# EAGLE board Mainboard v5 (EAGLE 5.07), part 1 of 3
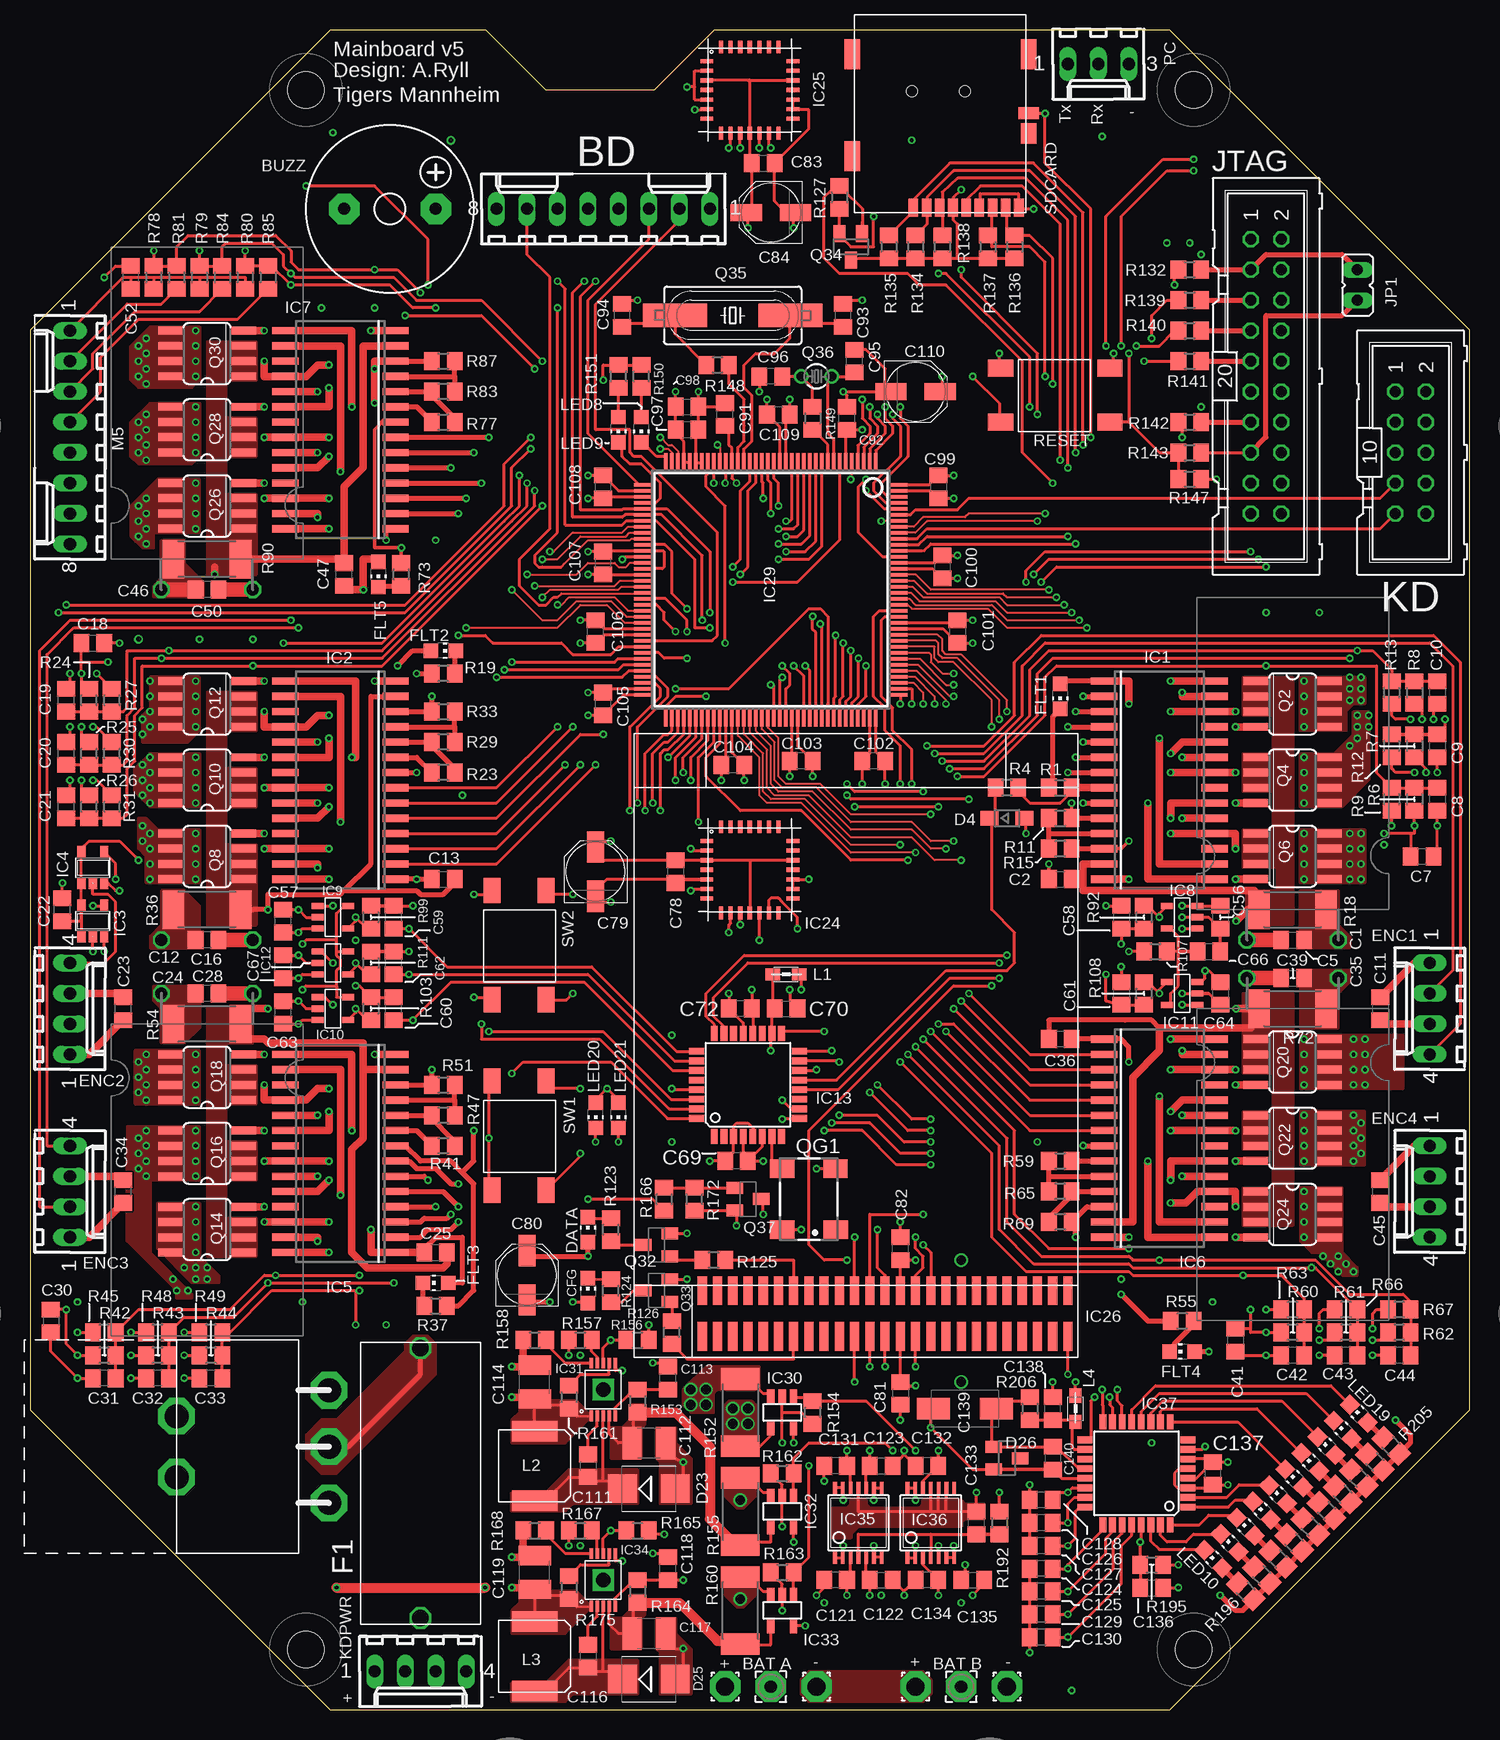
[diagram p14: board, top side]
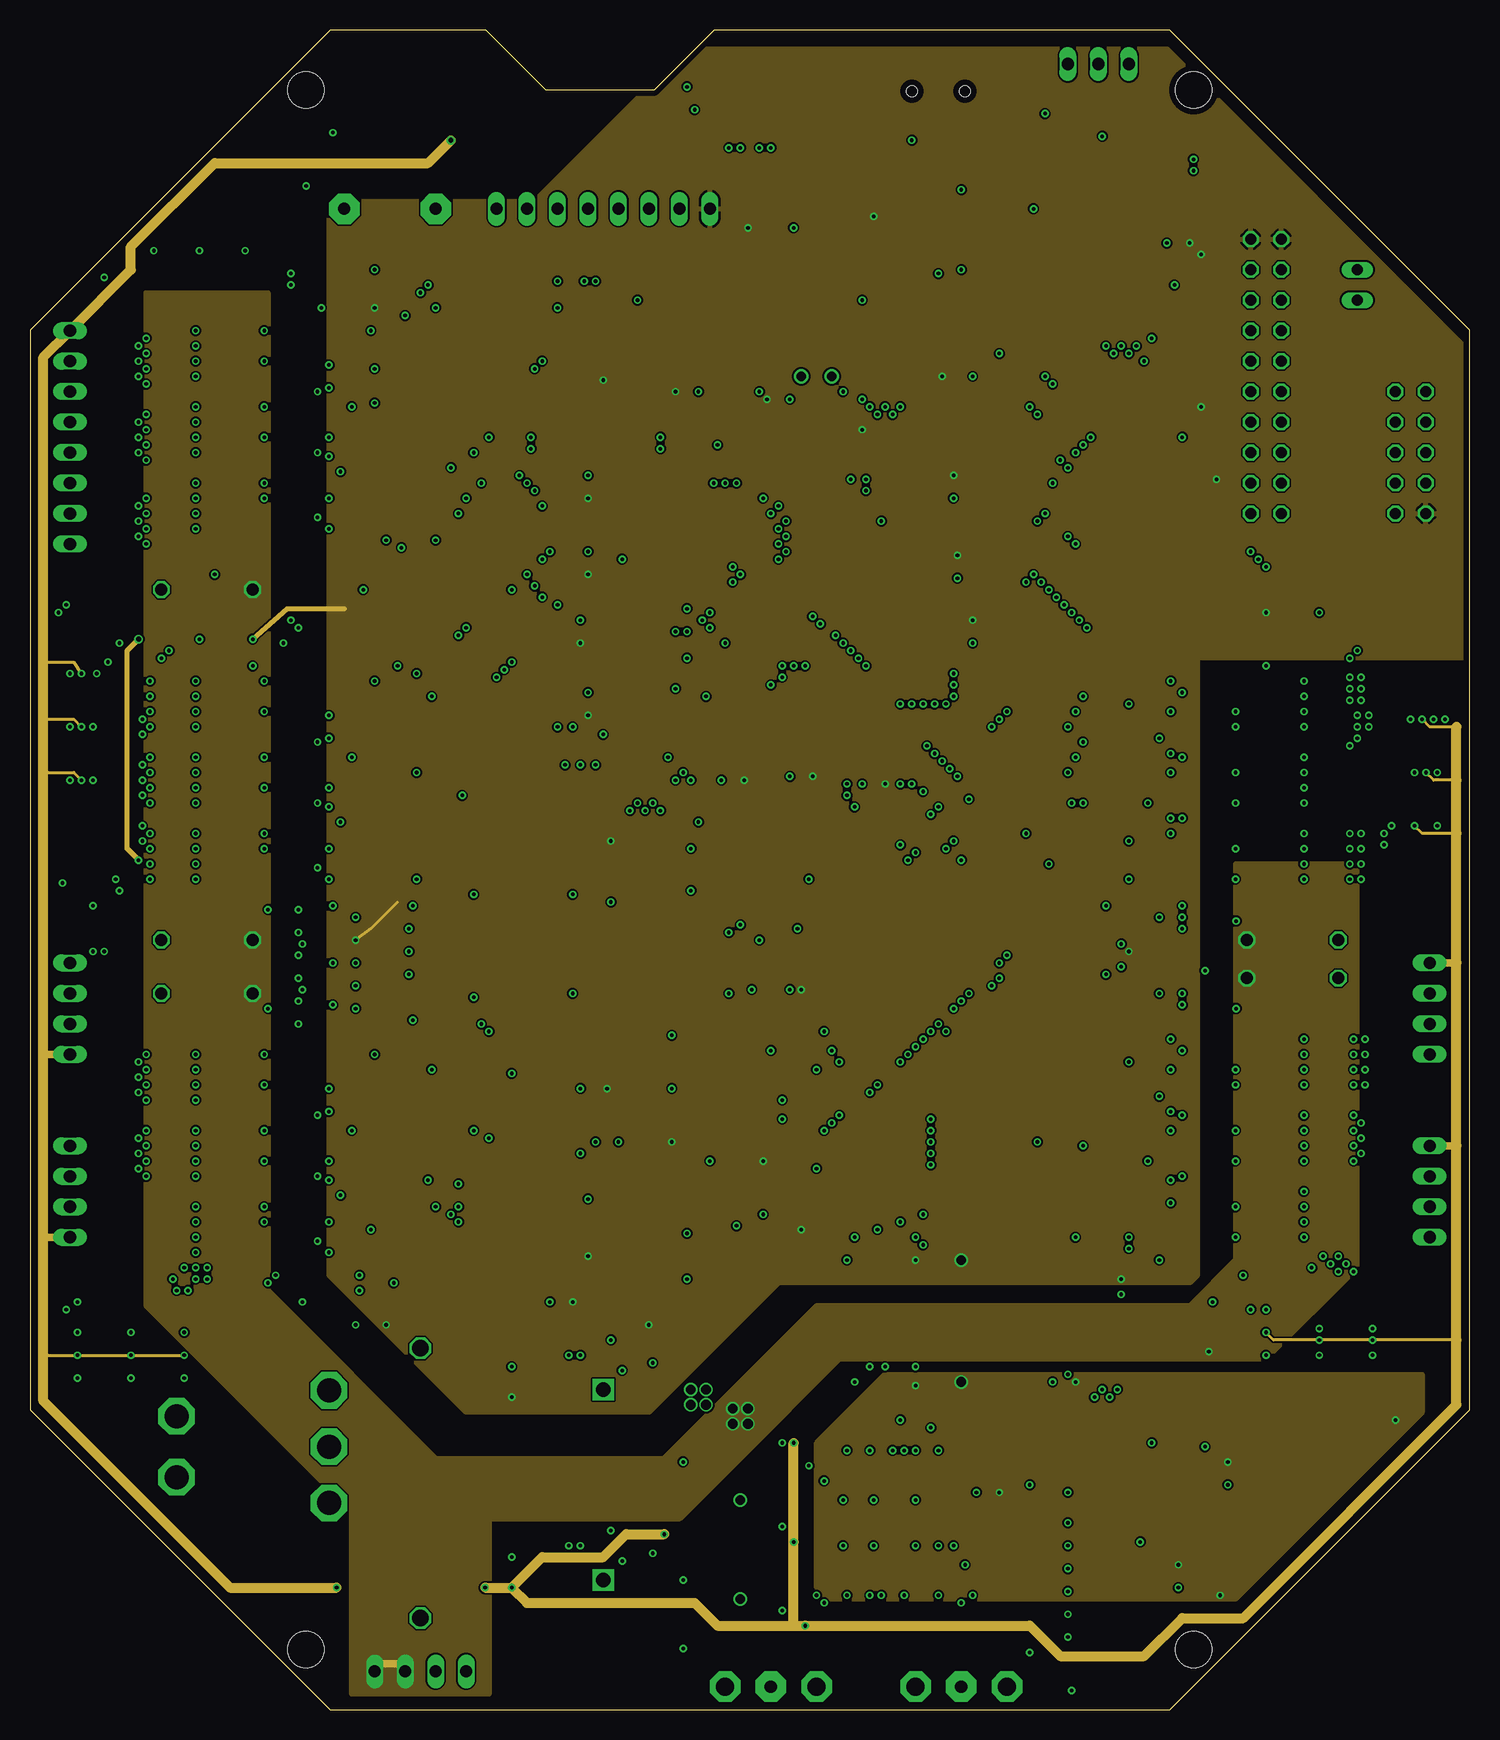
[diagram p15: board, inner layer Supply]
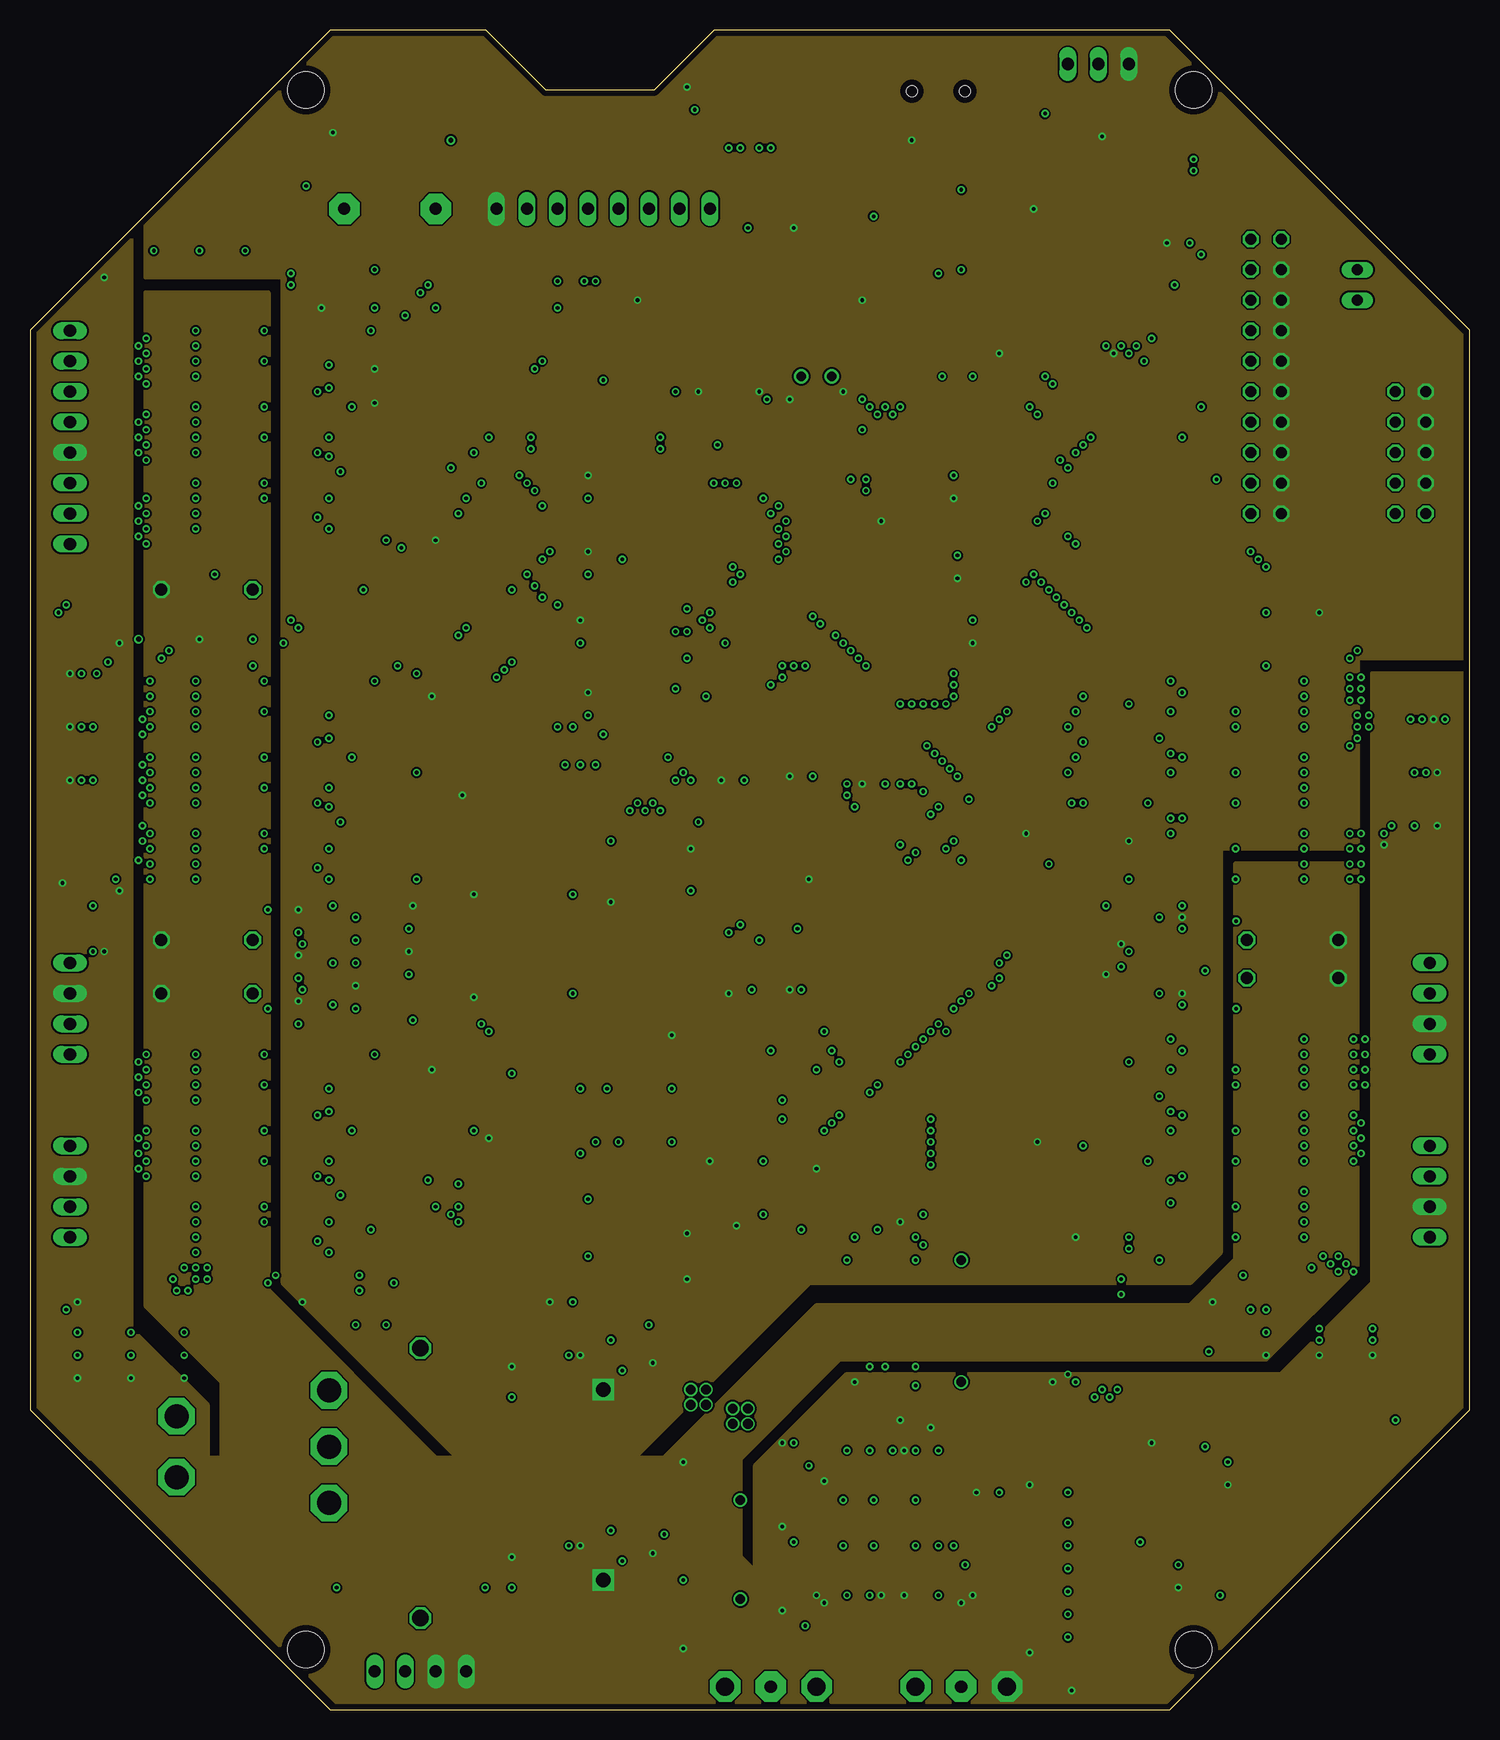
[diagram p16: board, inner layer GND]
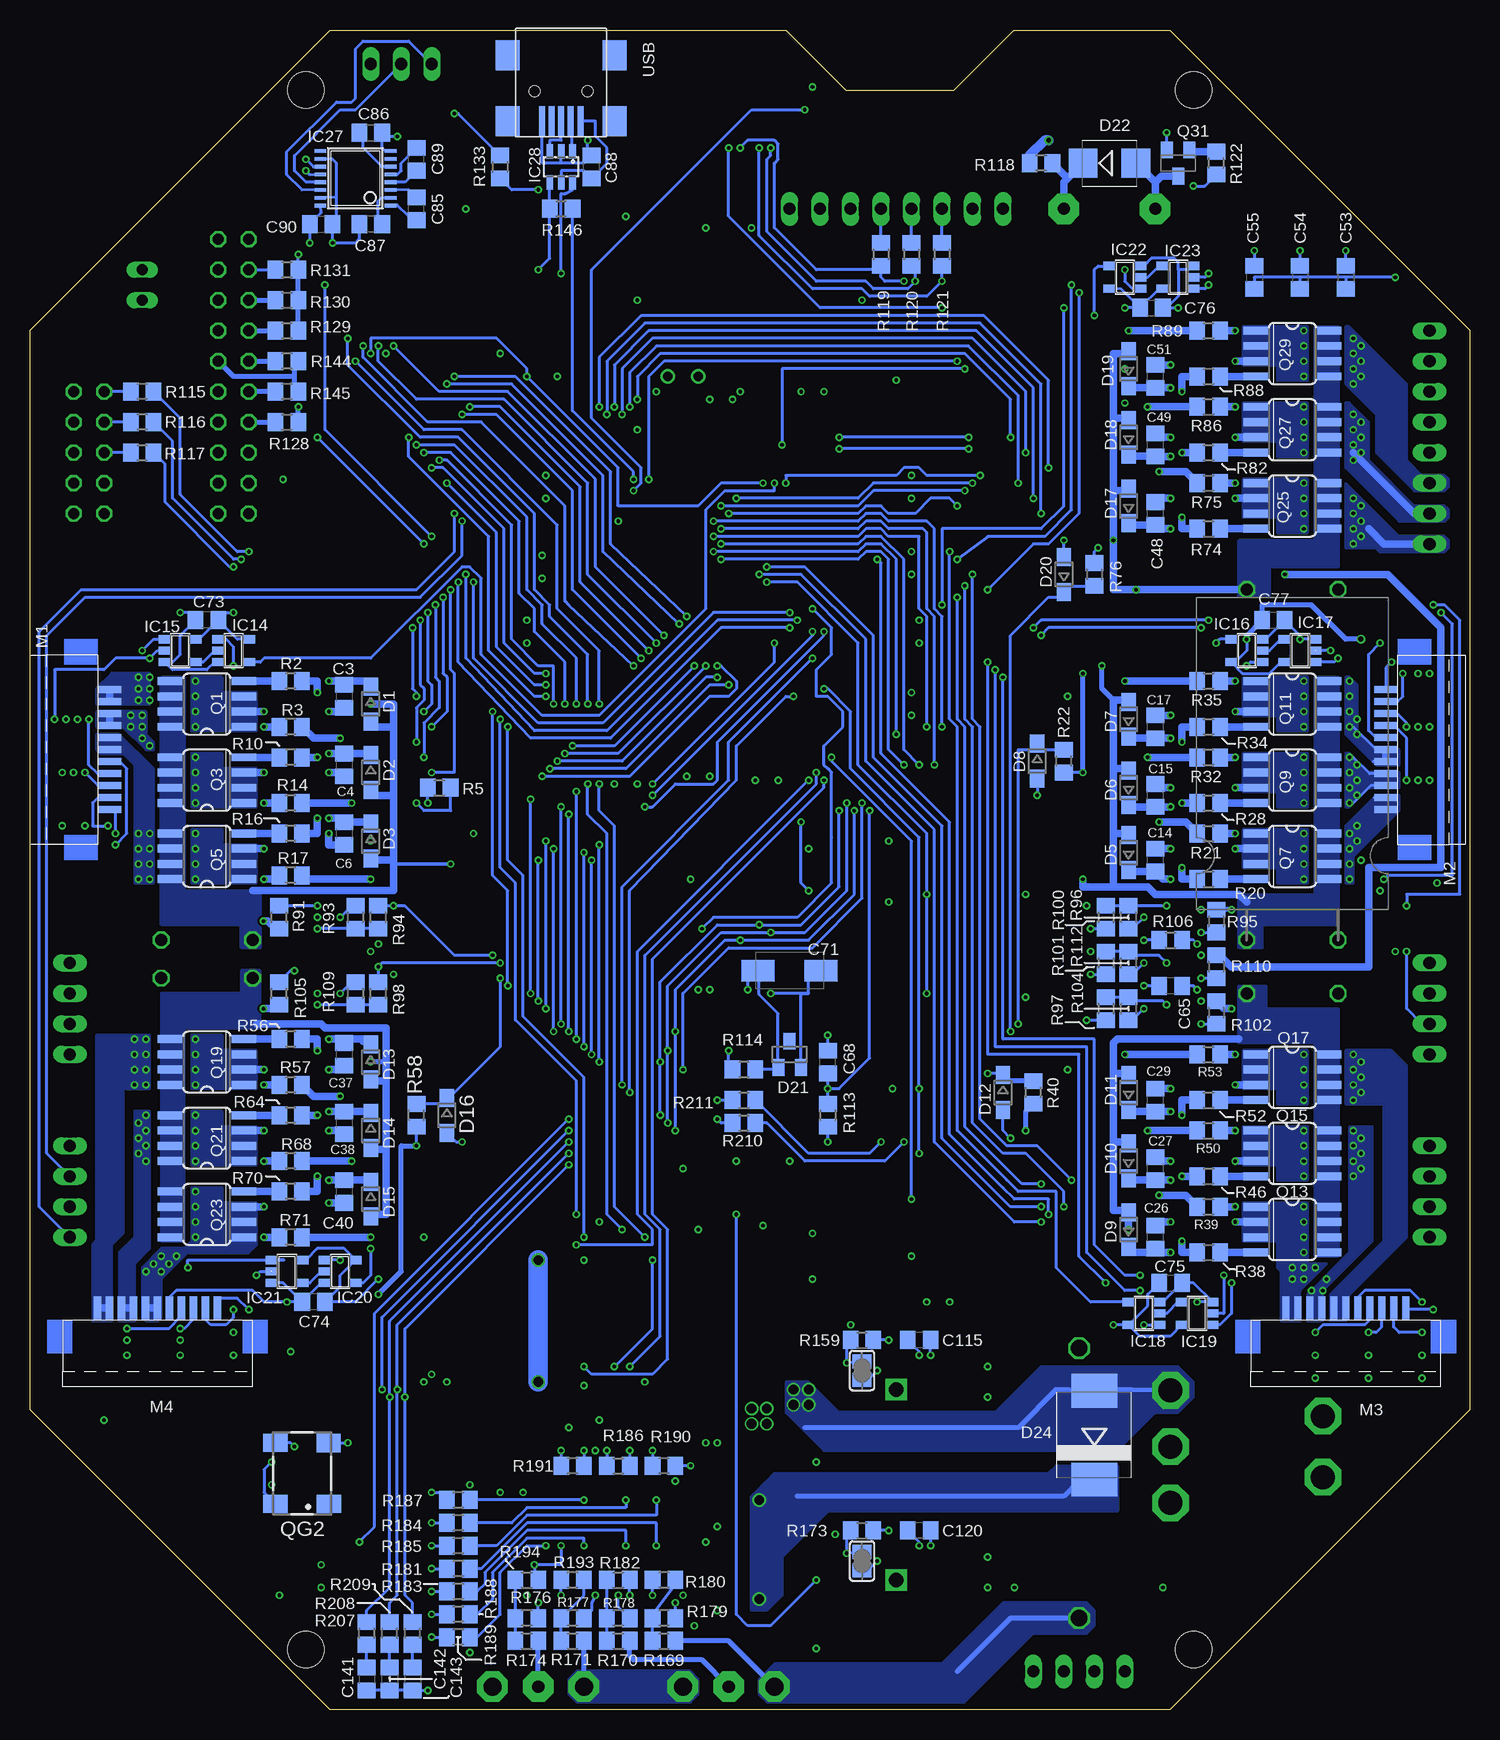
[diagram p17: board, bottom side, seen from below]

Size 120 x 140 mm. Coordinates in mm from the lower left corner, seen from the top.
Outline: 25,0 95,0 120,25 120,115 95,140 57,140 52,135 43,135 38,140 25,140 0,115 0,25 25,0
Copper layers (1+2*15+16): Top 0.035mm / dielectric 1.5mm / Supply 0.035mm / dielectric 0.15mm / GND 0.035mm / dielectric 0.2mm / Bottom 0.035mm
Design rules "PCB-POOL *": minimum track width 6mil, minimum drill 12mil, track to track 6mil, track to pad 6mil, pad to pad 6mil, via to via 6mil, smd to smd 6mil, copper to edge 20mil, drill to drill 8mil, minimum pad ring 8mil, minimum via ring 6mil, stop-mask expansion 3mil, vias tented up to drill 0mil, thermal gap 8mil
Net classes: 0 default: width 0.152 mm, clearance 0.152 mm
Holes 3 mm at 23,5 97,5 97,135 23,135
bKeepout: area 121.5,103.5 to 128.5,110.5

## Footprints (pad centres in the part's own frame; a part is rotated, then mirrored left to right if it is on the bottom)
2,54/1,0 = drill 1.016 pad 2.54 octagon: 1 0,0
2,54/1,5 = drill 1.5 pad 2.54 octagon: P$1 0,0
6410-08 = drill 1.016 long: 1 8.89,0; 2 6.35,0; 3 3.81,0; 4 1.27,0; 5 -1.27,0; 6 -3.81,0; 7 -6.35,0; 8 -8.89,0
F/CM12P = drill 1.016 pad 2.54 octagon: + 3.81,0; - -3.81,0
C25-16L = drill 1 octagon: A -3.81,-2.54; B 3.81,-2.54
C0805 = smd 1.3 x 1.5: 1 -0.95,0; 2 0.95,0
C/6032-28W = smd 2.75 x 1.8: + 2.625,0; - -2.625,0
PANASONIC_C = smd 2.6 x 1.4: + 2.05,0; - -2.05,0
C1210 = smd 1.6 x 2.7: 1 -1.4,0; 2 1.4,0
CHIP-LED0805 = smd 1.2 x 1.2: A 0,-1.05; C 0,1.05
SOD323-W = smd 1.5 x 1.2: A 1.45,0; C -1.45,0
SOT23 = smd 1 x 1.4: 1 -0.95,-1.1; 2 0.95,-1.1; 3 0,1.1
SMB = smd 2.4 x 2.4: A 2.2,0; C -2.2,0
SMC = smd 2.8 x 3.8: A 3.7,0; C -3.7,0
6410-04 = drill 1.016 long: 1 3.81,0; 2 1.27,0; 3 -1.27,0; 4 -3.81,0
FUSE20X5-2 = drill 1.4 octagon: P$1 0,0; P$2 22.5,0
SO28W = smd 0.6 x 2.2: 1 -8.255,-4.6; 2 -6.985,-4.6; 3 -5.715,-4.6; 4 -4.445,-4.6; 5 -3.175,-4.6; 6 -1.905,-4.6; 7 -0.635,-4.6; 8 0.635,-4.6; 9 1.905,-4.6; 10 3.175,-4.6; 11 4.445,-4.6; 12 5.715,-4.6; 13 6.985,-4.6; 14 8.255,-4.6; 15 8.255,4.6; 16 6.985,4.6; 17 5.715,4.6; 18 4.445,4.6; 19 3.175,4.6; 20 1.905,4.6; 21 0.635,4.6; 22 -0.635,4.6; 23 -1.905,4.6; 24 -3.175,4.6; 25 -4.445,4.6; 26 -5.715,4.6; 27 -6.985,4.6; 28 -8.255,4.6
SOT23-5 = smd 0.69 x 0.99: 1 -0.95,-1.29; 2 0,-1.29; 3 0.95,-1.29; 4 0.95,1.3; 5 -0.95,1.3
SOT23-5' = smd 1.016 x 0.508: 1 -1.27,0.953; 2 -1.27,0; 3 -1.27,-0.953; 4 1.27,-0.953; 5 1.27,0.953
TQFP32-08 = smd 1.27 x 0.559: 1 -4.293,2.8; 2 -4.293,2; 3 -4.293,1.2; 4 -4.293,0.4; 5 -4.293,-0.4; 6 -4.293,-1.2; 7 -4.293,-2; 8 -4.293,-2.8; 17 4.293,-2.8; 18 4.293,-2; 19 4.293,-1.2; 20 4.293,-0.4; 21 4.293,0.4; 22 4.293,1.2; 23 4.293,2; 24 4.293,2.8 | smd 0.559 x 1.27: 9 -2.8,-4.293; 10 -2,-4.293; 11 -1.2,-4.293; 12 -0.4,-4.293; 13 0.4,-4.293; 14 1.2,-4.293; 15 2,-4.293; 16 2.8,-4.293; 25 2.8,4.293; 26 2,4.293; 27 1.2,4.293; 28 0.4,4.293; 29 -0.4,4.293; 30 -1.2,4.293; 31 -2,4.293; 32 -2.8,4.293
QFPN-28 = smd 1.05 x 0.35: 1 -3.6,2.4; 2 -3.6,1.6; 3 -3.6,0.8; 4 -3.6,0; 5 -3.6,-0.8; 6 -3.6,-1.6; 7 -3.6,-2.4; 15 3.6,-2.4; 16 3.6,-1.6; 17 3.6,-0.8; 18 3.6,0; 19 3.6,0.8; 20 3.6,1.6; 21 3.6,2.4 | smd 0.35 x 1.05: 8 -2.4,-3.6; 9 -1.6,-3.6; 10 -0.8,-3.6; 11 0,-3.6; 12 0.8,-3.6; 13 1.6,-3.6; 14 2.4,-3.6; 22 2.4,3.6; 23 1.6,3.6; 24 0.8,3.6; 25 0,3.6; 26 -0.8,3.6; 27 -1.6,3.6; 28 -2.4,3.6
PINHEAD-1.27-50 = smd 2.4 x 0.76: 1 2.54,0; 2 -1.27,0; 3 2.54,-1.27; 4 -1.27,-1.27; 5 2.54,-2.54; 6 -1.27,-2.54; 7 2.54,-3.81; 8 -1.27,-3.81; 9 2.54,-5.08; 10 -1.27,-5.08; 11 2.54,-6.35; 12 -1.27,-6.35; 13 2.54,-7.62; 14 -1.27,-7.62; 15 2.54,-8.89; 16 -1.27,-8.89; 17 2.54,-10.16; 18 -1.27,-10.16; 19 2.54,-11.43; 20 -1.27,-11.43; 21 2.54,-12.7; 22 -1.27,-12.7; 23 2.54,-13.97; 24 -1.27,-13.97; 25 2.54,-15.24; 26 -1.27,-15.24; 27 2.54,-16.51; 28 -1.27,-16.51; 29 2.54,-17.78; 30 -1.27,-17.78; 31 2.54,-19.05; 32 -1.27,-19.05; 33 2.54,-20.32; 34 -1.27,-20.32; 35 2.54,-21.59; 36 -1.27,-21.59; 37 2.54,-22.86; 38 -1.27,-22.86; 39 2.54,-24.13; 40 -1.27,-24.13; 41 2.54,-25.4; 42 -1.27,-25.4; 43 2.54,-26.67; 44 -1.27,-26.67; 45 2.54,-27.94; 46 -1.27,-27.94; 47 2.54,-29.21; 48 -1.27,-29.21; 49 2.54,-30.48; 50 -1.27,-30.48
TSSOP16 = smd 0.305 x 0.991: 1 -2.275,-2.918; 2 -1.625,-2.918; 3 -0.975,-2.918; 4 -0.325,-2.918; 5 0.325,-2.918; 6 0.975,-2.918; 7 1.625,-2.918; 8 2.275,-2.918; 9 2.275,2.918; 10 1.625,2.918; 11 0.975,2.918; 12 0.325,2.918; 13 -0.325,2.918; 14 -0.975,2.918; 15 -1.625,2.918; 16 -2.275,2.918
SOT23-6L = smd 0.55 x 1.2: 1 -0.95,-1.3; 2 0,-1.3; 3 0.95,-1.3; 4 0.95,1.3; 5 0,1.3; 6 -0.95,1.3
SQFP-S-20X20-144 = smd 0.3 x 1.6: 1 -8.75,-10.6; 2 -8.25,-10.6; 3 -7.75,-10.6; 4 -7.25,-10.6; 5 -6.75,-10.6; 6 -6.25,-10.6; 7 -5.75,-10.6; 8 -5.25,-10.6; 9 -4.75,-10.6; 10 -4.25,-10.6; 11 -3.75,-10.6; 12 -3.25,-10.6; 13 -2.75,-10.6; 14 -2.25,-10.6; 15 -1.75,-10.6; 16 -1.25,-10.6; 17 -0.75,-10.6; 18 -0.25,-10.6; 19 0.25,-10.6; 20 0.75,-10.6; 21 1.25,-10.6; 22 1.75,-10.6; 23 2.25,-10.6; 24 2.75,-10.6; 25 3.25,-10.6; 26 3.75,-10.6; 27 4.25,-10.6; 28 4.75,-10.6; 29 5.25,-10.6; 30 5.75,-10.6; 31 6.25,-10.6; 32 6.75,-10.6; 33 7.25,-10.6; 34 7.75,-10.6; 35 8.25,-10.6; 36 8.75,-10.6; 73 8.75,10.6; 74 8.25,10.6; 75 7.75,10.6; 76 7.25,10.6; 77 6.75,10.6; 78 6.25,10.6; 79 5.75,10.6; 80 5.25,10.6; 81 4.75,10.6; 82 4.25,10.6; 83 3.75,10.6; 84 3.25,10.6; 85 2.75,10.6; 86 2.25,10.6; 87 1.75,10.6; 88 1.25,10.6; 89 0.75,10.6; 90 0.25,10.6; 91 -0.25,10.6; 92 -0.75,10.6; 93 -1.25,10.6; 94 -1.75,10.6; 95 -2.25,10.6; 96 -2.75,10.6; 97 -3.25,10.6; 98 -3.75,10.6; 99 -4.25,10.6; 100 -4.75,10.6; 101 -5.25,10.6; 102 -5.75,10.6; 103 -6.25,10.6; 104 -6.75,10.6; 105 -7.25,10.6; 106 -7.75,10.6; 107 -8.25,10.6; 108 -8.75,10.6 | smd 1.6 x 0.3: 37 10.6,-8.75; 38 10.6,-8.25; 39 10.6,-7.75; 40 10.6,-7.25; 41 10.6,-6.75; 42 10.6,-6.25; 43 10.6,-5.75; 44 10.6,-5.25; 45 10.6,-4.75; 46 10.6,-4.25; 47 10.6,-3.75; 48 10.6,-3.25; 49 10.6,-2.75; 50 10.6,-2.25; 51 10.6,-1.75; 52 10.6,-1.25; 53 10.6,-0.75; 54 10.6,-0.25; 55 10.6,0.25; 56 10.6,0.75; 57 10.6,1.25; 58 10.6,1.75; 59 10.6,2.25; 60 10.6,2.75; 61 10.6,3.25; 62 10.6,3.75; 63 10.6,4.25; 64 10.6,4.75; 65 10.6,5.25; 66 10.6,5.75; 67 10.6,6.25; 68 10.6,6.75; 69 10.6,7.25; 70 10.6,7.75; 71 10.6,8.25; 72 10.6,8.75; 109 -10.6,8.75; 110 -10.6,8.25; 111 -10.6,7.75; 112 -10.6,7.25; 113 -10.6,6.75; 114 -10.6,6.25; 115 -10.6,5.75; 116 -10.6,5.25; 117 -10.6,4.75; 118 -10.6,4.25; 119 -10.6,3.75; 120 -10.6,3.25; 121 -10.6,2.75; 122 -10.6,2.25; 123 -10.6,1.75; 124 -10.6,1.25; 125 -10.6,0.75; 126 -10.6,0.25; 127 -10.6,-0.25; 128 -10.6,-0.75; 129 -10.6,-1.25; 130 -10.6,-1.75; 131 -10.6,-2.25; 132 -10.6,-2.75; 133 -10.6,-3.25; 134 -10.6,-3.75; 135 -10.6,-4.25; 136 -10.6,-4.75; 137 -10.6,-5.25; 138 -10.6,-5.75; 139 -10.6,-6.25; 140 -10.6,-6.75; 141 -10.6,-7.25; 142 -10.6,-7.75; 143 -10.6,-8.25; 144 -10.6,-8.75
SOT23-5'' = smd 0.6 x 1.2: 1 -0.95,-1.306; 2 0,-1.306; 3 0.95,-1.306; 4 0.95,1.306; 5 -0.95,1.306
MSOP10 = smd 0.9 x 0.3: 1 -2.2,1; 2 -2.2,0.5; 3 -2.2,0; 4 -2.2,-0.5; 5 -2.2,-1; 6 2.2,-1; 7 2.2,-0.5; 8 2.2,0; 9 2.2,0.5; 10 2.2,1 | drill 1.2 pad 1.8 square: 11 0,0
TSSOP14 = smd 0.305 x 0.991: 1 -1.95,-2.918; 2 -1.3,-2.918; 3 -0.65,-2.918; 4 0,-2.918; 5 0.65,-2.918; 6 1.3,-2.918; 7 1.95,-2.918; 8 1.95,2.918; 9 1.3,2.918; 10 0.65,2.918; 11 0,2.918; 12 -0.65,2.918; 13 -1.3,2.918; 14 -1.95,2.918
JP1 = drill 0.914 long: 1 0,-1.27; 2 0,1.27
ML20 = drill 0.914 octagon: 1 -11.43,-1.27; 2 -11.43,1.27; 3 -8.89,-1.27; 4 -8.89,1.27; 5 -6.35,-1.27; 6 -6.35,1.27; 7 -3.81,-1.27; 8 -3.81,1.27; 9 -1.27,-1.27; 10 -1.27,1.27; 11 1.27,-1.27; 12 1.27,1.27; 13 3.81,-1.27; 14 3.81,1.27; 15 6.35,-1.27; 16 6.35,1.27; 17 8.89,-1.27; 18 8.89,1.27; 19 11.43,-1.27; 20 11.43,1.27
ML10 = drill 0.914 octagon: 1 -5.08,-1.27; 2 -5.08,1.27; 3 -2.54,-1.27; 4 -2.54,1.27; 5 0,-1.27; 6 0,1.27; 7 2.54,-1.27; 8 2.54,1.27; 9 5.08,-1.27; 10 5.08,1.27
0805 = smd 1.2 x 1: 1 -1.1,0; 2 1.1,0
L-ELL6 = smd 1.7 x 3.8: P$1 -2.9,0; P$2 2.9,0
MOLEX11 = smd 0.6 x 1.9: 1 5,3; 2 4,3; 3 3,3; 4 2,3; 5 1,3; 6 0,3; 7 -1,3; 8 -2,3; 9 -3,3; 10 -4,3; 11 -5,3
6410-03 = drill 1.016 long: 1 2.54,0; 2 0,0; 3 -2.54,0
SOIC8 = smd 0.66 x 2.032: 1 -1.905,-3.073; 2 -0.635,-3.073; 3 0.635,-3.073; 4 1.905,-3.073; 5 1.905,3.073; 6 0.635,3.073; 7 -0.635,3.073; 8 -1.905,3.073
SOT23-BEC = smd 1 x 1.4: B -0.95,-1.1; C 0,1.1; E 0.95,-1.1
HC49UP = smd 5.334 x 1.93: 1 -4.826,0; 2 4.826,0
TC26V = drill 0.813 round: 1 -1.27,0; 2 1.27,0
SM77H = smd 1.524 x 2.032: 1 -2.545,-2.232; 2 2.535,-2.212; 3 2.545,2.232; 4 -2.535,2.212
R0805 = smd 1.3 x 1.5: 1 -0.95,0; 2 0.95,0
R2512 = smd 1.8 x 3.2: 1 -2.8,0; 2 2.8,0
BUTTON4 = smd 1.4 x 2.1: 1 4.5,9.1; 2 4.5,0; 3 0,9.1; 4 0,0
MICRO-SD = smd 0.8 x 1.5: 1 4.9,0.4; 2 6,0.4; 3 7.1,0.4; 4 8.2,0.4; 5 9.3,0.4; 6 10.4,0.4; 7 11.5,0.4; 8 12.6,0.4; COM 13.7,0.4 | smd 1.7 x 1: CD 14.5,8.3 | smd 1.3 x 2.5: P$10 14.5,13.2; P$11 -0.2,13.2; P$12 -0.2,4.7 | smd 1.3 x 1.7: P$14 14.5,6.6
SJ = smd 1.168 x 1.6: 1 -0.762,0; 2 0.762,0
TYCO-SW = drill 2 pad 3.048 octagon: 1 -4.699,12.7; 2 0,12.7; 3 4.699,12.7; MNT1 -2.54,0; MNT2 2.54,0
USB-BMINI = smd 2.5 x 0.5: 1 0,1.6; 2 0,0.8; 3 0,0; 4 0,-0.8; 5 0,-1.6 | smd 2.5 x 2: P$6 0,4.45; P$7 0,-4.45; P$8 -5.5,4.45; P$9 -5.5,-4.45 | hole 0.9: -2.5,2.2; -2.5,-2.2

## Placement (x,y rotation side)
BAT1#  [2,54/1,0]  61.75,1.91 0 top
BAT1+  [2,54/1,5]  57.94,1.91 0 top
BAT1-  [2,54/1,5]  65.56,1.91 0 top
BAT2#  [2,54/1,0]  77.63,1.91 0 top
BAT2+  [2,54/1,5]  73.82,1.91 0 top
BAT2-  [2,54/1,5]  81.44,1.91 0 top
BD  MOLEX8  [6410-08]  47.78,125.09 0 top
BUZZ  F/CM12P  [F/CM12P]  30.01,125.09 0 top
C1  3300u/25V  [C25-16L]  105.25,66.67 0 top
C2  4u7  [C0805]  85.89,69.22 0 top
C3  4u7  [C0805]  93.82,84.45 270 bottom
C4  4u7  [C0805]  93.82,78.74 270 bottom
C5  10u  [C0805]  105.25,64.14 0 top
C6  4u7  [C0805]  93.82,73.03 270 bottom
C7  100n  [C0805]  116.05,71.12 0 top
C8  1n  [C0805]  117.32,75.88 270 top
C9  1n  [C0805]  117.32,80.33 270 top
C10  1n  [C0805]  117.32,84.77 270 top
C11  100n  [C0805]  112.56,58.42 270 top
C12  3300u/25V  [C25-16L]  14.77,66.67 0 bottom
C13  4u7  [C0805]  34.45,69.22 0 top
C14  4u7  [C0805]  26.2,70.8 90 bottom
C15  4u7  [C0805]  26.2,76.2 90 bottom
C16  10u  [C0805]  14.77,64.14 180 top
C17  4u7  [C0805]  26.2,81.92 90 bottom
C18  100n  [C0805]  5.24,88.9 0 top
C19  1n  [C0805]  3.02,84.14 90 top
C20  1n  [C0805]  3.02,79.69 90 top
C21  1n  [C0805]  3.02,75.25 90 top
C22  100n  [C0805]  2.7,66.67 90 top
C23  100n  [C0805]  7.78,58.42 90 top
C24  3300u/25V  [C25-16L]  14.77,57.15 180 top
C25  4u7  [C0805]  33.81,38.1 0 top
C26  4u7  [C0805]  26.2,39.37 90 bottom
C27  4u7  [C0805]  26.2,45.09 90 bottom
C28  10u  [C0805]  14.77,59.69 180 top
C29  4u7  [C0805]  26.2,50.8 90 bottom
C30  100n  [C0805]  1.75,32.38 270 top
C31  1n  [C0805]  6.19,27.62 180 top
C32  1n  [C0805]  10.64,27.62 180 top
C33  1n  [C0805]  15.08,27.62 180 top
C34  100n  [C0805]  7.78,43.18 90 top
C35  3300u/25V  [C25-16L]  105.25,58.42 180 top
C36  4u7  [C0805]  85.89,55.88 180 top
C37  4u7  [C0805]  93.82,54.61 270 bottom
C38  4u7  [C0805]  93.82,48.9 270 bottom
C39  10u  [C0805]  105.25,60.96 0 top
C40  4u7  [C0805]  93.82,43.18 270 bottom
C41  100n  [C0805]  100.49,30.8 270 top
C42  1n  [C0805]  105.25,29.53 180 top
C43  1n  [C0805]  109.7,29.53 180 top
C44  1n  [C0805]  114.14,29.53 180 top
C45  100n  [C0805]  112.56,43.18 270 top
C46  3300u/25V  [C25-16L]  14.77,95.89 0 top
C47  4u7  [C0805]  26.2,94.61 90 top
C48  4u7  [C0805]  26.2,99.69 90 bottom
C49  4u7  [C0805]  26.2,105.41 90 bottom
C50  10u  [C0805]  14.77,93.34 180 top
C51  4u7  [C0805]  26.2,111.12 90 bottom
C52  100n  [C0805]  8.41,119.38 90 top
C53  1n  [C0805]  10.32,119.38 270 bottom
C54  1n  [C0805]  14.13,119.38 270 bottom
C55  1n  [C0805]  17.94,119.38 270 bottom
C56  1u  [C0805]  99.22,66.04 270 top
C57  1u  [C0805]  21.11,65.72 90 top
C58  100n  [C0805]  90.97,66.04 270 top
C59  100n  [C0805]  30.32,66.04 90 top
C60  100n  [C0805]  30.32,58.42 90 top
C61  100n  [C0805]  90.97,59.69 270 top
C62  100n  [C0805]  30.32,62.23 90 top
C63  1u  [C0805]  21.11,58.1 90 top
C64  1u  [C0805]  99.22,59.69 270 top
C65  4u7  [C0805]  24.92,60.33 180 bottom
C66  4u7  [C0805]  98.27,63.18 0 top
C67  1u  [C0805]  21.11,61.91 90 top
C68  100n  [C0805]  53.5,53.98 90 bottom
C69  100n  [C0805]  58.9,45.72 180 top
C70  100n  [C0805]  63.03,58.42 0 top
C71  10u  [C/6032-28W]  56.67,61.59 180 bottom
C72  100n  [C0805]  59.22,58.42 180 top
C73  100n  [C0805]  105.25,90.81 180 bottom
C74  100n  [C0805]  96.36,33.97 180 bottom
C75  100n  [C0805]  24.92,35.56 0 bottom
C76  100n  [C0805]  26.51,116.84 0 bottom
C77  100n  [C0805]  16.35,90.81 0 bottom
C78  100n  [C0805]  53.82,69.85 270 top
C79  10u  [PANASONIC_C]  47.15,69.85 90 top
C80  10u  [PANASONIC_C]  41.44,36.2 90 top
C81  100n  [C0805]  72.55,26.35 270 top
C82  100n  [C0805]  72.55,38.42 90 top
C83  100n  [C0805]  61.12,128.91 0 top
C84  10u  [PANASONIC_C]  61.75,124.78 180 top
C85  100n  [C0805]  87.79,125.09 90 bottom
C86  100n  [C0805]  91.6,131.44 0 bottom
C87  100n  [C0805]  91.6,123.83 180 bottom
C88  100n  [C0805]  73.19,128.59 90 bottom
C89  100n  [C0805]  87.79,129.22 90 bottom
C90  100n  [C0805]  95.73,123.83 0 bottom
C91  100n  [C0805]  57.94,107.95 90 top
C92  100n  [C0805]  68.11,107.63 90 top
C93  18p  [C0805]  67.79,116.2 90 top
C94  18p  [C0805]  49.37,116.2 90 top
C95  6p  [C0805]  68.74,112.39 90 top
C96  6p  [C0805]  61.75,111.12 180 top
C97  1u  [C0805]  54.77,106.68 0 top
C98  100n  [C0805]  54.77,108.58 0 top
C99  100n  [C0805]  75.72,101.92 270 top
C100  100n  [C0805]  76.04,95.25 270 top
C101  100n  [C0805]  77.31,89.85 270 top
C102  100n  [C0805]  70.33,79.06 180 top
C103  100n  [C0805]  64.3,79.06 180 top
C104  100n  [C0805]  58.58,78.74 180 top
C105  100n  [C0805]  47.78,83.82 90 top
C106  100n  [C0805]  47.15,89.85 90 top
C107  100n  [C0805]  47.78,95.57 90 top
C108  100n  [C0805]  47.78,101.92 90 top
C109  100n  [C0805]  62.39,107.95 0 top
C110  10µ  [PANASONIC_C]  73.82,109.86 0 top
C111  470n  [C0805]  46.52,20.32 270 top
C112  10u  [C1210]  51.59,22.23 0 top
C113  100n  [C0805]  53.18,27.62 90 top
C114  47u  [C1210]  42.07,27.3 90 top
C115  470p  [C0805]  45.88,30.8 180 bottom
C116  470n  [C0805]  46.52,4.45 270 top
C117  10u  [C1210]  51.59,6.35 0 top
C118  100n  [C0805]  53.18,11.75 90 top
C119  47u  [C1210]  42.07,11.43 90 top
C120  470p  [C0805]  45.88,14.92 180 bottom
C121  100n  [C0805]  67.15,10.79 180 top
C122  100n  [C0805]  70.96,10.79 0 top
C123  100n  [C0805]  70.96,20.32 0 top
C124  100n  [C0805]  84.3,11.75 180 top
C125  100n  [C0805]  84.3,9.84 180 top
C126  100n  [C0805]  84.3,15.56 180 top
C127  100n  [C0805]  84.3,13.65 180 top
C128  100n  [C0805]  84.3,17.46 180 top
C129  100n  [C0805]  84.3,7.94 180 top
C130  100n  [C0805]  84.3,6.03 180 top
C131  100n  [C0805]  67.15,20.32 180 top
C132  100n  [C0805]  74.77,20.32 180 top
C133  4u7  [C0805]  78.9,15.56 90 top
C134  100n  [C0805]  74.77,10.79 180 top
C135  100n  [C0805]  78.58,10.79 0 top
C136  100n  [C0805]  93.5,10.16 0 top
C137  100n  [C0805]  98.58,19.68 270 top
C138  100n  [C0805]  85.25,25.08 90 top
C139  10u  [C/6032-28W]  77.95,25.08 0 top
C140  100n  [C0805]  85.25,20.95 270 top
C141  100p  [C0805]  91.92,2.54 270 bottom
C142  100p  [C0805]  90.01,2.54 270 bottom
C143  100p  [C0805]  88.11,2.54 270 bottom
CFG  rd, 2mA  [CHIP-LED0805]  46.52,34.92 0 top
D1  BAT41  [SOD323-W]  91.6,83.82 270 bottom
D2  BAT41  [SOD323-W]  91.6,78.11 270 bottom
D3  BAT41  [SOD323-W]  91.6,72.39 270 bottom
D4  Z-3.3V  [SOD323-W]  81.44,74.3 0 top
D5  BAT41  [SOD323-W]  28.42,71.44 90 bottom
D6  BAT41  [SOD323-W]  28.42,76.83 90 bottom
D7  BAT41  [SOD323-W]  28.42,82.55 90 bottom
D8  Z-3.3V  [SOD323-W]  36.04,79.06 270 bottom
D9  BAT41  [SOD323-W]  28.42,40.01 90 bottom
D10  BAT41  [SOD323-W]  28.42,45.72 90 bottom
D11  BAT41  [SOD323-W]  28.42,51.44 90 bottom
D12  Z-3.3V  [SOD323-W]  38.9,51.44 270 bottom
D13  BAT41  [SOD323-W]  91.6,53.98 270 bottom
D14  BAT41  [SOD323-W]  91.6,48.26 270 bottom
D15  BAT41  [SOD323-W]  91.6,42.55 270 bottom
D16  Z-3.3V  [SOD323-W]  85.25,49.53 270 bottom
D17  BAT41  [SOD323-W]  28.42,100.33 90 bottom
D18  BAT41  [SOD323-W]  28.42,106.05 90 bottom
D19  BAT41  [SOD323-W]  28.42,111.76 90 bottom
D20  Z-3.3V  [SOD323-W]  33.81,94.61 90 bottom
D21  LM4040-2.048  [SOT23]  56.67,54.61 0 bottom
D22  MBRS240  [SMB]  30.01,128.91 0 bottom
D23  MBRS240  [SMB]  51.59,18.41 0 top
D24  MBRS340  [SMC]  31.27,22.86 90 bottom
D25  MBRS240  [SMB]  51.59,2.54 0 top
D26  LM4040-2.048  [SOT23]  81.44,20.95 270 top
DATA  gr, 2mA  [CHIP-LED0805]  46.52,40.01 0 top
ENC1  22-27-2041-04  [6410-04]  116.68,58.42 90 top
ENC2  22-27-2041-04  [6410-04]  3.34,58.42 270 top
ENC3  22-27-2041-04  [6410-04]  3.34,43.18 270 top
ENC4  22-27-2041-04  [6410-04]  116.68,43.18 90 top
F1  [FUSE20X5-2]  32.55,7.62 90 top
FLT1  rd  [CHIP-LED0805]  85.89,84.45 180 top
FLT2  rd  [CHIP-LED0805]  34.45,88.27 270 top
FLT3  rd  [CHIP-LED0805]  33.81,35.56 90 top
FLT4  rd  [CHIP-LED0805]  96.05,29.84 90 top
FLT5  rd  [CHIP-LED0805]  29.05,94.61 180 top
IC1  IR2130S  [SO28W]  94.14,77.47 270 top
IC2  IR2130S  [SO28W]  25.88,77.47 90 top
IC3  74LVC1G08DBV  [SOT23-5]  5.24,65.72 0 top
IC4  74LVC1G08DBV  [SOT23-5]  5.24,70.17 0 top
IC5  IR2130S  [SO28W]  25.88,46.35 90 top
IC6  IR2130S  [SO28W]  94.14,47.62 270 top
IC7  IR2130S  [SO28W]  25.88,106.68 90 top
IC8  AD8691  [SOT23-5']  96.05,66.04 180 top
IC9  AD8691  [SOT23-5']  25.24,66.04 0 top
IC10  AD8691  [SOT23-5']  25.24,58.42 0 top
IC11  AD8691  [SOT23-5']  96.05,59.69 180 top
IC12  AD8691  [SOT23-5']  25.24,62.23 0 top
IC13  MEGA48/88/168-AU  [TQFP32-08]  59.85,52.07 90 top
IC14  74AHC1G86DBV  [SOT23-5]  103.03,88.27 270 bottom
IC15  74AHC1G86DBV  [SOT23-5]  107.47,88.27 270 bottom
IC16  74AHC1G86DBV  [SOT23-5]  18.57,88.27 90 bottom
IC17  74AHC1G86DBV  [SOT23-5]  14.13,88.27 90 bottom
IC18  74AHC1G86DBV  [SOT23-5]  27.15,33.02 90 bottom
IC19  74AHC1G86DBV  [SOT23-5]  22.7,33.02 90 bottom
IC20  74AHC1G86DBV  [SOT23-5]  94.14,36.51 270 bottom
IC21  74AHC1G86DBV  [SOT23-5]  98.58,36.51 270 bottom
IC22  74AHC1G86DBV  [SOT23-5]  28.73,119.38 90 bottom
IC23  74AHC1G86DBV  [SOT23-5]  24.29,119.38 90 bottom
IC24  LIS3LV02DQ  [QFPN-28]  60,70 0 top
IC25  LIS3LV02DQ  [QFPN-28]  60,135 0 top
IC26  HW86012  [PINHEAD-1.27-50]  56.04,32.38 90 top
IC27  MAX3232CUE  [TSSOP16]  92.87,127.64 90 bottom
IC28  USBLC6-2  [SOT23-6L]  75.72,128.59 180 bottom
IC29  [SQFP-S-20X20-144]  61.75,93.34 180 top
IC30  INA139  [SOT23-5'']  62.71,24.77 180 top
IC31  LT3480  [MSOP10]  47.78,26.67 90 top
IC32  INA139  [SOT23-5'']  62.71,16.51 180 top
IC33  INA139  [SOT23-5'']  62.71,8.26 180 top
IC34  LT3480  [MSOP10]  47.78,10.79 90 top
IC35  AD8648  [TSSOP14]  69.06,15.56 0 top
IC36  AD8648  [TSSOP14]  75.09,15.56 0 top
IC37  MEGA48/88/168-AU  [TQFP32-08]  92.23,19.68 180 top
JP1  [JP1]  110.65,118.75 0 top
JTAG  [ML20]  103.03,111.12 270 top
KD  [ML10]  115.09,104.78 270 top
KDPWR  MOLEX4  [6410-04]  32.55,3.17 180 top
L1  10u  [0805]  63.03,61.28 180 top
L2  6u8  [L-ELL6]  42.07,20.32 270 top
L3  6u8  [L-ELL6]  42.07,4.45 270 top
L4  10u  [0805]  87.16,25.08 270 top
LED8  rd  [CHIP-LED0805]  50.96,106.68 180 top
LED9  gr  [CHIP-LED0805]  49.05,106.68 180 top
LED10  rd  [CHIP-LED0805]  98.65,12.55 45 top
LED11  rd  [CHIP-LED0805]  100,13.89 45 top
LED12  or  [CHIP-LED0805]  101.34,15.24 45 top
LED13  or  [CHIP-LED0805]  102.69,16.59 45 top
LED14  ye  [CHIP-LED0805]  104.04,17.93 45 top
LED15  ye  [CHIP-LED0805]  105.38,19.28 45 top
LED16  gr  [CHIP-LED0805]  106.73,20.63 45 top
LED17  gr  [CHIP-LED0805]  108.08,21.98 45 top
LED18  gr  [CHIP-LED0805]  109.43,23.32 45 top
LED19  gr  [CHIP-LED0805]  110.77,24.67 45 top
LED20  rd  [CHIP-LED0805]  47.15,49.53 180 top
LED21  gr  [CHIP-LED0805]  49.05,49.53 180 top
M1  [MOLEX11]  116.36,80.01 270 bottom
M2  [MOLEX11]  3.97,80.01 90 bottom
M3  [MOLEX11]  10.32,30.48 0 bottom
M4  [MOLEX11]  109.38,30.48 0 bottom
M5  MOLEX8  [6410-08]  3.34,106.05 90 top
PC  MOLEX3  [6410-03]  89.06,137.16 180 top
Q1  FDS6670  [SOIC8]  105.25,83.82 90 bottom
Q2  FDS6670  [SOIC8]  105.25,83.82 270 top
Q3  FDS6670  [SOIC8]  105.25,77.47 90 bottom
Q4  FDS6670  [SOIC8]  105.25,77.47 270 top
Q5  FDS6670  [SOIC8]  105.25,71.12 90 bottom
Q6  FDS6670  [SOIC8]  105.25,71.12 270 top
Q7  FDS6670  [SOIC8]  14.77,71.12 270 bottom
Q8  FDS6670  [SOIC8]  14.77,71.12 90 top
Q9  FDS6670  [SOIC8]  14.77,77.47 270 bottom
Q10  FDS6670  [SOIC8]  14.77,77.47 90 top
Q11  FDS6670  [SOIC8]  14.77,83.82 270 bottom
Q12  FDS6670  [SOIC8]  14.77,83.82 90 top
Q13  FDS6670  [SOIC8]  14.77,40.01 270 bottom
Q14  FDS6670  [SOIC8]  14.77,40.01 90 top
Q15  FDS6670  [SOIC8]  14.77,46.35 270 bottom
Q16  FDS6670  [SOIC8]  14.77,46.35 90 top
Q17  FDS6670  [SOIC8]  14.77,52.7 270 bottom
Q18  FDS6670  [SOIC8]  14.77,52.7 90 top
Q19  FDS6670  [SOIC8]  105.25,53.98 90 bottom
Q20  FDS6670  [SOIC8]  105.25,53.98 270 top
Q21  FDS6670  [SOIC8]  105.25,47.62 90 bottom
Q22  FDS6670  [SOIC8]  105.25,47.62 270 top
Q23  FDS6670  [SOIC8]  105.25,41.27 90 bottom
Q24  FDS6670  [SOIC8]  105.25,41.27 270 top
Q25  FDS6670  [SOIC8]  14.77,100.33 270 bottom
Q26  FDS6670  [SOIC8]  14.77,100.33 90 top
Q27  FDS6670  [SOIC8]  14.77,106.68 270 bottom
Q28  FDS6670  [SOIC8]  14.77,106.68 90 top
Q29  FDS6670  [SOIC8]  14.77,113.03 270 bottom
Q30  FDS6670  [SOIC8]  14.77,113.03 90 top
Q31  BCW66  [SOT23-BEC]  24.29,128.91 180 bottom
Q32  BCW66  [SOT23-BEC]  52.23,38.73 90 top
Q33  BCW66  [SOT23-BEC]  52.23,34.92 90 top
Q34  BSH205  [SOT23]  68.42,121.92 180 top
Q35  12Mhz  [HC49UP]  58.58,116.2 180 top
Q36  32.768kHz  [TC26V]  65.56,111.12 180 top
Q37  BCW66  [SOT23-BEC]  59.85,42.55 270 top
QG1  12MHz  [SM77H]  64.93,42.55 90 top
QG2  12MHz  [SM77H]  97.31,19.68 90 bottom
R1  1k  [R0805]  85.89,76.83 0 top
R2  10  [R0805]  98.27,85.72 180 bottom
R3  10  [R0805]  98.27,81.92 180 bottom
R4  10k  [R0805]  81.44,76.83 180 top
R5  1k  [R0805]  85.89,76.83 0 bottom
R6  4k7  [R0805]  115.41,75.88 270 top
R7  4k7  [R0805]  115.41,80.33 270 top
R8  4k7  [R0805]  115.41,84.77 270 top
R9  100  [R0805]  113.51,75.88 270 top
R10  10  [R0805]  98.27,79.38 180 bottom
R11  3k9  [R0805]  85.89,74.3 0 top
R12  100  [R0805]  113.51,80.33 270 top
R13  100  [R0805]  113.51,84.77 270 top
R14  10  [R0805]  98.27,75.56 180 bottom
R15  1k  [R0805]  85.89,71.75 180 top
R16  10  [R0805]  98.27,73.03 180 bottom
R17  10  [R0805]  98.27,69.53 180 bottom
R18  0R005 2W  [R2512]  105.25,66.67 0 top
R19  1k  [R0805]  34.45,86.36 180 top
R20  10  [R0805]  21.75,69.22 0 bottom
R21  10  [R0805]  21.75,73.03 0 bottom
R22  10k  [R0805]  33.81,79.06 90 bottom
R23  1k  [R0805]  34.45,78.11 180 top
R24  4k7  [R0805]  4.92,84.14 90 top
R25  4k7  [R0805]  4.92,79.69 90 top
R26  4k7  [R0805]  4.92,75.25 90 top
R27  100  [R0805]  6.83,84.14 90 top
R28  10  [R0805]  21.75,75.56 0 bottom
R29  3k9  [R0805]  34.45,80.64 180 top
R30  100  [R0805]  6.83,79.69 90 top
R31  100  [R0805]  6.83,75.25 90 top
R32  10  [R0805]  21.75,79.38 0 bottom
R33  1k  [R0805]  34.45,83.19 0 top
R34  10  [R0805]  21.75,81.92 0 bottom
R35  10  [R0805]  21.75,85.72 0 bottom
R36  0R005 2W  [R2512]  14.77,66.67 180 top
R37  1k  [R0805]  33.81,33.66 0 top
R38  10  [R0805]  21.75,38.1 0 bottom
R39  10  [R0805]  21.75,41.91 0 bottom
R40  10k  [R0805]  36.35,51.44 90 bottom
R41  1k  [R0805]  34.45,46.99 180 top
R42  4k7  [R0805]  6.19,29.53 180 top
R43  4k7  [R0805]  10.64,29.53 180 top
R44  4k7  [R0805]  15.08,29.53 180 top
R45  100  [R0805]  6.19,31.43 180 top
R46  10  [R0805]  21.75,44.45 0 bottom
R47  3k9  [R0805]  34.45,49.53 180 top
R48  100  [R0805]  10.64,31.43 180 top
R49  100  [R0805]  15.08,31.43 180 top
R50  10  [R0805]  21.75,48.26 0 bottom
R51  1k  [R0805]  34.45,52.07 0 top
R52  10  [R0805]  21.75,50.8 0 bottom
R53  10  [R0805]  21.75,54.61 0 bottom
R54  0R005 2W  [R2512]  14.77,57.15 180 top
R55  1k  [R0805]  96.05,32.38 180 top
R56  10  [R0805]  98.27,55.88 180 bottom
R57  10  [R0805]  98.27,52.07 180 bottom
R58  10k  [R0805]  87.79,49.53 90 bottom
R59  1k  [R0805]  85.89,45.72 0 top
R60  4k7  [R0805]  105.25,31.43 180 top
R61  4k7  [R0805]  109.7,31.43 180 top
R62  4k7  [R0805]  114.14,31.43 180 top
R63  100  [R0805]  105.25,33.34 180 top
R64  10  [R0805]  98.27,49.53 180 bottom
R65  3k9  [R0805]  85.89,43.18 180 top
R66  100  [R0805]  109.7,33.34 180 top
R67  100  [R0805]  114.14,33.34 180 top
R68  10  [R0805]  98.27,45.72 180 bottom
R69  1k  [R0805]  85.89,40.64 180 top
R70  10  [R0805]  98.27,43.18 180 bottom
R71  10  [R0805]  98.27,39.37 180 bottom
R72  0R005 2W  [R2512]  105.25,58.42 0 top
R73  1k  [R0805]  30.96,94.61 90 top
R74  10  [R0805]  21.75,98.42 0 bottom
R75  10  [R0805]  21.75,102.23 0 bottom
R76  10k  [R0805]  31.27,94.61 270 bottom
R77  1k  [R0805]  34.45,107.31 0 top
R78  4k7  [R0805]  10.32,119.38 270 top
R79  4k7  [R0805]  14.13,119.38 270 top
R80  4k7  [R0805]  17.94,119.38 270 top
R81  100  [R0805]  12.23,119.38 270 top
R82  10  [R0805]  21.75,104.78 0 bottom
R83  3k9  [R0805]  34.45,109.86 180 top
R84  100  [R0805]  16.04,119.38 270 top
R85  100  [R0805]  19.84,119.38 270 top
R86  10  [R0805]  21.75,108.58 0 bottom
R87  1k  [R0805]  34.45,112.39 0 top
R88  10  [R0805]  21.75,111.12 0 bottom
R89  10  [R0805]  21.75,114.94 0 bottom
R90  0R005 2W  [R2512]  14.77,95.89 180 top
R91  100k  [R0805]  99.22,66.04 90 bottom
R92  1k  [R0805]  92.87,66.04 90 top
R93  39k  [R0805]  92.87,66.04 270 bottom
R94  100  [R0805]  90.97,66.04 90 bottom
R95  100k  [R0805]  21.11,65.72 270 bottom
R96  100  [R0805]  30.32,66.04 270 bottom
R97  100  [R0805]  30.32,58.42 270 bottom
R98  100  [R0805]  90.97,59.69 90 bottom
R99  1k  [R0805]  28.42,66.04 270 top
R100  39k  [R0805]  28.42,66.04 90 bottom
R101  100  [R0805]  30.32,62.23 270 bottom
R102  100k  [R0805]  21.11,58.1 270 bottom
R103  1k  [R0805]  28.42,58.42 270 top
R104  39k  [R0805]  28.42,58.42 90 bottom
R105  100k  [R0805]  99.22,59.69 90 bottom
R106  10  [R0805]  24.92,64.14 0 bottom
R107  10  [R0805]  93.82,63.18 0 top
R108  1k  [R0805]  92.87,59.69 90 top
R109  39k  [R0805]  92.87,59.69 270 bottom
R110  100k  [R0805]  21.11,61.91 270 bottom
R111  1k  [R0805]  28.42,62.23 270 top
R112  39k  [R0805]  28.42,62.23 90 bottom
R113  10k  [R0805]  53.5,49.53 270 bottom
R114  1k  [R0805]  60.48,53.34 180 bottom
R115  10  [R0805]  110.65,109.86 180 bottom
R116  10  [R0805]  110.65,107.31 180 bottom
R117  10  [R0805]  110.65,104.78 0 bottom
R118  220  [R0805]  35.72,128.91 180 bottom
R119  10  [R0805]  49.05,121.28 270 bottom
R120  10  [R0805]  46.52,121.28 270 bottom
R121  10  [R0805]  43.98,121.28 270 bottom
R122  10k  [R0805]  21.11,128.91 90 bottom
R123  120  [R0805]  48.42,40.01 90 top
R124  120  [R0805]  48.42,34.92 90 top
R125  10k  [R0805]  56.99,37.47 180 top
R126  10k  [R0805]  53.5,31.43 90 top
R127  4k7  [R0805]  67.47,126.05 270 top
R128  10k  [R0805]  98.58,107.31 0 bottom
R129  10k  [R0805]  98.58,114.94 0 bottom
R130  10k  [R0805]  98.58,117.47 0 bottom
R131  10k  [R0805]  98.58,120.02 0 bottom
R132  470  [R0805]  96.68,120.02 0 top
R133  47k  [R0805]  80.81,128.59 270 bottom
R134  47k  [R0805]  73.82,121.92 270 top
R135  47k  [R0805]  71.6,121.92 270 top
R136  47k  [R0805]  82.08,121.92 270 top
R137  47k  [R0805]  79.85,121.92 270 top
R138  47k  [R0805]  76.04,121.92 270 top
R139  470  [R0805]  96.68,117.47 0 top
R140  470  [R0805]  96.68,114.94 0 top
R141  470  [R0805]  96.68,112.39 0 top
R142  470  [R0805]  96.68,107.31 0 top
R143  470  [R0805]  96.68,104.78 0 top
R144  10k  [R0805]  98.58,112.39 180 bottom
R145  10k  [R0805]  98.58,109.86 180 bottom
R146  1k5  [R0805]  75.72,125.09 0 bottom
R147  10k  [R0805]  96.68,102.55 0 top
R148  270  [R0805]  57.31,112.08 0 top
R149  100k  [R0805]  65.25,107.63 270 top
R150  120  [R0805]  50.96,111.12 90 top
R151  120  [R0805]  49.05,111.12 90 top
R152  0R002 3W  [R2512]  59.22,24.77 270 top
R153  100k  [R0805]  50.64,25.72 270 top
R154  27k  [R0805]  65.25,24.77 90 top
R155  0R1  [R2512]  59.22,16.51 270 top
R156  316k  [R0805]  50.64,30.8 0 top
R157  14k  [R0805]  45.88,30.8 0 top
R158  100k  [R0805]  42.07,30.8 0 top
R159  100k 0.1%  [R0805]  50.64,30.8 0 bottom
R160  0R1  [R2512]  59.22,8.26 90 top
R161  100k  [R0805]  44.93,26.04 270 top
R162  20k  [R0805]  62.71,19.68 0 top
R163  20k  [R0805]  62.71,11.43 0 top
R164  100k  [R0805]  50.64,9.84 270 top
R165  536k  [R0805]  50.64,14.92 0 top
R166  1k  [R0805]  52.87,42.55 90 top
R167  14k  [R0805]  45.88,14.92 0 top
R168  100k  [R0805]  42.07,14.92 0 top
R169  200k  [R0805]  67.15,5.71 0 bottom
R170  270k  [R0805]  70.96,5.71 0 bottom
R171  240k  [R0805]  74.77,5.71 0 bottom
R172  10k  [R0805]  55.41,42.55 90 top
R173  100k 0.1%  [R0805]  50.64,14.92 0 bottom
R174  110k  [R0805]  78.58,5.71 0 bottom
R175  100k  [R0805]  44.93,10.16 270 top
R176  100k  [R0805]  78.58,7.62 180 bottom
R177  75k  [R0805]  74.77,7.62 180 bottom
R178  51k  [R0805]  70.96,7.62 180 bottom
R179  27k  [R0805]  67.15,7.62 180 bottom
R180  1k  [R0805]  67.15,10.79 180 bottom
R181  100  [R0805]  84.3,11.75 180 bottom
R182  1k  [R0805]  70.96,10.79 0 bottom
R183  100  [R0805]  84.3,9.84 180 bottom
R184  100  [R0805]  84.3,15.56 180 bottom
R185  100  [R0805]  84.3,13.65 180 bottom
R186  1k  [R0805]  70.96,20.32 0 bottom
R187  100  [R0805]  84.3,17.46 180 bottom
R188  100  [R0805]  84.3,7.94 180 bottom
R189  100  [R0805]  84.3,6.03 180 bottom
R190  1k  [R0805]  67.15,20.32 180 bottom
R191  1k  [R0805]  74.77,20.32 180 bottom
R192  10  [R0805]  80.81,15.56 270 top
R193  1k  [R0805]  74.77,10.79 180 bottom
R194  1k  [R0805]  78.58,10.79 0 bottom
R195  10k  [R0805]  93.5,12.06 0 top
R196  120  [R0805]  101.34,9.85 315 top
R197  120  [R0805]  102.69,11.2 315 top
R198  120  [R0805]  104.04,12.55 315 top
R199  120  [R0805]  105.38,13.89 315 top
R200  120  [R0805]  106.73,15.24 315 top
R201  120  [R0805]  108.08,16.59 315 top
R202  120  [R0805]  109.43,17.93 315 top
R203  120  [R0805]  110.77,19.28 315 top
R204  120  [R0805]  112.12,20.63 315 top
R205  120  [R0805]  113.47,21.98 315 top
R206  1k  [R0805]  83.34,25.08 270 top
R207  100  [R0805]  91.92,6.35 90 bottom
R208  100  [R0805]  90.01,6.35 90 bottom
R209  100  [R0805]  88.11,6.35 90 bottom
R210  120  [R0805]  60.48,48.9 0 bottom
R211  120  [R0805]  60.48,50.8 0 bottom
RESET  BUTTON4  [BUTTON4]  90.01,107.31 90 top
SDCARD  MICRO-SD  [MICRO-SD]  68.74,124.78 0 top
SJ1  [SJ]  50.64,28.26 270 bottom
SJ2  [SJ]  50.64,12.38 270 bottom
SW1  BUTTON4  [BUTTON4]  43.02,52.39 180 top
SW2  BUTTON4  [BUTTON4]  43.02,68.26 180 top
SW3  SPDTTYCO  [TYCO-SW]  12.23,21.91 270 top
USB  USB-BMINI  [USB-BMINI]  75.72,132.4 270 bottom

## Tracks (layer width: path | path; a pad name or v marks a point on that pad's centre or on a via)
+3V3  (via drill 0.3, 0.41, 0.81)
  Top 0.254: v70.33,124.46 70.33,121.92 68.42,121.92 67.47,122.87 Q34.2 R127.2 | 59.85,124.78 60.8,124.78 60.8,125.09 60.17,125.09 C83.1 | v59.85,123.51 59.85,124.78 | 59.85,124.78 C84.+ | IC26.28 C81.1 72.55,26.99 v73.82,26.99 | IC26.27 C82.1 v73.82,37.47 | v45.24,33.97 46.52,33.97 CFG.A | L2.P$1 42.07,25.4 | 42.07,25.4 C114.1 42.07,26.04 | IC31.1 45.56,24.45 R161.2 44.61,25.08 44.29,25.4 42.07,25.4 | R156.2 51.59,30.48 v51.59,32.07 | IC29.32 IC29.33 54.5,105.67 54.14,106.05 54.14,106.36 C97.1 C98.1 v53.82,109.85 v53.82,109.86 | IC29.17 62.5,106.89 C109.1 v61.44,109.22 | IC29.6 68,106.58 C92.1 v69.37,106.68 v69.38,106.68 | IC29.144 74.95,102.09 C99.1 v76.99,102.87 v77,102.87 | IC29.131 75.44,95.59 C100.1 v77.31,96.2 | IC29.121 77.11,90.59 C101.1 v78.58,90.8 v78.58,90.81 | IC29.108 70.5,79.83 C102.1 v71.28,77.16 v71.28,77.15 | IC29.95 64,80.3 C103.1 v65.25,77.79 | IC29.84 58.5,79.77 C104.1 v59.53,77.47 | IC29.52 47.81,94.59 C107.1 v46.52,94.62 v46.52,94.61 | IC29.62 47.84,89.59 C106.1 v45.88,88.9 | IC29.72 49.51,84.59 C105.1 v46.52,82.87 | IC29.39 47.91,101.09 C108.1 v46.52,100.97 | 60,70.8 IC24.11 | 60,70.8 IC24.3 C78.1 47.15,70.8 C79.+ 47.64,72.39 v48.42,72.39 | 60,70.8 IC24.19 | R150.2 R151.2 47.79,112.08 v47.78,110.81 | C110.+ 76.04,109.86 v76.04,111.12 | C83.1 | C83.1 60,129.07 IC25.11 60,135.8 59.85,135.8 | 59.85,135.8 IC25.3 | 59.85,135.8 IC25.19 | R147.2 v98.9,102.55 | R107.1 v91.6,63.18 | IC13.4 59.45,46.12 C69.1 61.05,46.92 | 61.05,46.92 IC13.6 | 61.05,46.92 C69.1 v61.12,45.72 | L1.1 64.3,61.11 v64.3,60.01 | R192.1 v80.81,18.1 | IC37.4 97.23,19.29 C137.1 | IC37.6 98.33,20.89 C137.1 | C137.1 v99.85,20.64 v99.86,20.64
  Top 0.254: L4.1 v87.16,27.3 | R195.2 v95.73,12.06 | R198.2 | R198.2 | R197.2 | QG1.4 63.04,40.01 v64.3,40.01 | C22.1 4.29,65.72 4.26,65.75 4.26,67 IC3.5 | IC3.5 IC3.1 | IC3.5 IC4.1 IC4.5 4.29,71.76 4.92,72.39 7.46,72.39 v9.05,70.8 | LED20.A 47.15,50.8 v48.1,51.75 49.05,50.8 LED21.A | R203.2 | R202.2 | R201.2 | R200.2
  Top 0.406: DATA.A v46.52,37.78 41.9,37.78 C80.+ | 101.09,8.26 R196.2 R197.2 | v99.22,9.53 100.49,8.26 101.12,8.26 | v113.83,24.13 115.09,22.86 115.09,22.26 R205.2 R204.2 R203.2 R202.2 R201.2 R200.2 R199.2 R198.2 R197.2
  Top 0.61: 42.07,26.04 v40.16,26.04
  Supply 0.254: v27.15,64.14 28.42,65.09 30.64,67.31
  Supply 0.406: v18.57,89.22 21.43,91.76 26.2,91.76 | v9.05,70.8 8.1,71.75 8.1,88.27 v9.05,89.22
  Bottom 0.254: IC27.16 95.73,124.78 C90.1 v96.68,122.24 | C76.1 29.03,118.41 IC22.5 | C76.1 v28.73,116.84 | R131.2 v97.63,121.28 | R128.2 | C73.1 104.3,91.44 v103.03,91.44 | IC17.5 15.73,87.3 16.67,86.36 18.92,86.36 IC16.5 19.52,87.31 18.57,88.27 v18.57,89.22 | R106.1 v27.15,64.14 | IC19.5 24.96,31.11 27.49,31.11 IC18.5 | C75.1 26.83,34.6 26.83,33.66 28.41,32.07 IC18.5 | IC18.5 v29.69,32.07 | v53.5,47.31 R113.2 | QG2.4 100.49,18.09 100.49,20 v99.86,20.64 | IC23.5 25.87,118.43 C76.1 | IC21.5 97,37.46 96.05,38.42 93.8,38.42 IC20.5 92.87,37.46 94.14,36.2 94.14,35.24 C74.1 92.87,33.97 v90.97,35.88 | IC14.5 102.71,89.22 C73.1 | IC15.5 105.89,89.22 C73.1
  Bottom 0.406: 17.3,90.49 | R131.2 R130.2 R129.2 | R128.2 v97.63,108.58 | v9.05,89.22 10.32,89.22 13.18,92.08 17.3,92.08 17.3,90.49 | 17.3,90.49 16.99,90.81 C77.1 18.57,89.53 v18.57,89.22
  Bottom 1.626: v77.63,27.3 v77.63,37.47
  pour Top (no thermals): 40.16,22.23 44.61,22.23 46.83,24.45 45.56,25.72 40.8,25.72 40.8,24.77 40.16,24.13
  pour Supply: 51.59,24.77 36.35,24.77 24.92,36.2 24.92,125.73 42.07,125.73 54.77,138.43 94.78,138.43 119.54,113.67 119.54,87.63 97.31,87.63 97.31,36.2 96.68,35.56 62.39,35.56
  pour Supply: 71.28,27.94 116.05,27.94 116.05,24.77 100.49,9.21 66.52,9.21 65.56,10.16 65.56,22.23
+3V3-A  (via drill 0.3)
  Top 0.254: C126.1 v86.52,15.56 86.52,17.14 87.06,17.68 IC37.23
  Bottom 0.254: v86.52,15.56 C126.1
+3V3-LOW
  Top 0.254: R153.2 | 50.33,24.45 R153.2 | 50.33,24.45 50.33,22.23 C112.1 49.05,22.23 48.28,23 IC31.4 | 50.33,24.45 50.33,24.77 R153.2 | 58.58,13.97 58.9,13.65 R155.2 59.53,13.97 61.75,13.97 61.75,14.92 IC32.4
  Top 0.813: 58.58,13.97 56.67,15.88 56.67,21.91 53.82,24.77 R153.2
  pour Top (no thermals): 50.96,20.95 50.96,23.5 51.28,23.81 51.28,25.4 50.01,25.4 50.01,24.13 49.37,23.5 48.42,23.5 48.42,20.95
+3V3-SHUNT  (via drill 0.3)
  Top 0.254: v71.92,21.59 71.28,22.23 64.93,22.23 63.66,20.95 R162.2 IC32.1
  Bottom 0.254: v71.92,21.59 R186.1
+5V  (via drill 0.3, 0.41)
  Top 0.254: 42.07,9.53 L3.P$1 | 42.07,9.53 C119.1 42.07,10.16 | 42.07,9.53 44.61,9.53 R175.2 45.56,8.57 IC34.1 | R165.2 51.91,14.61 v52.87,14.61 | IC30.5 v63.66,22.23 IC30.5 | IC32.5 63.66,15.24 v63.66,13.97 | IC33.5 63.66,6.99 v64.61,6.99 | v6.51,87.31 4.29,87.31 v4.29,86.36 | R24.2 4.29,85.72 v4.29,86.36 | R25.2 4.29,81.28 v4.29,81.92 | R26.2 4.29,76.83 v4.29,77.47 | C18.1 v4.29,86.36 | R42.2 v3.97,29.53 3.02,30.48 v3.02,33.34 C30.1 | v8.41,29.53 R43.2 | v12.86,29.53 R44.2 | R8.2 116.05,83.19 v116.05,82.55 | R7.2 116.36,78.42 v116.36,78.11 | 115.09,73.03 115.41,73.03 v115.41,73.66 R6.2 | 115.09,73.03 v112.87,73.03 | C7.1 115.1,73.02 115.09,73.03 | R61.2 108.11,30.8 v107.47,30.8 | R62.2 112.56,30.8 v111.92,30.8 | R60.2 v103.03,31.43 101.76,31.43 101.76,31.75 | 101.76,31.75 v101.76,33.34 | C41.1 101.76,31.75 | M5.1 7.78,119.38 8.41,119.38 | 8.41,119.38 10.32,119.38 | 10.32,119.38 14.13,119.38 | 14.13,119.38 17.94,119.38 R80.2 | 14.13,119.38 R79.2 | 8.41,119.38 C52.1 | 10.32,119.38 R78.2
  Top 0.61: v40.16,10.16 42.07,10.16 | C23.1 4.92,54.61 ENC2.1 | C34.1 4.92,39.37 ENC3.1 | C11.1 115.42,62.23 ENC1.1 | C45.1 115.42,46.99 ENC4.1 | IC30.5
  Top 0.813: v25.56,10.16 v37.94,10.16
  Supply 0.254: v4.29,86.36 3.65,87.31 1.11,87.31 | v4.29,81.92 3.65,82.55 1.11,82.55 | v4.29,77.47 3.65,78.11 1.11,78.11 | 1.11,29.53 v3.97,29.53 v8.41,29.53 v12.86,29.53 | v116.05,82.55 116.68,81.92 118.91,81.92 | v116.36,78.11 117,77.47 118.91,77.47 | v115.41,73.66 116.05,73.03 118.91,73.03 | 118.91,30.8 v111.92,30.8 v107.47,30.8 103.67,30.8 v103.03,31.43
  Supply 0.61: 1.11,39.37 ENC3.1 | 1.11,54.61 ENC2.1 | 118.91,46.99 ENC4.1 | 118.91,62.23 ENC1.1
  Supply 0.813: v52.87,14.61 49.69,14.61 47.78,12.7 42.7,12.7 v40.16,10.16 | v40.16,10.16 41.44,8.89 55.41,8.89 57.31,6.99 63.66,6.99 | 63.66,6.99 v63.66,13.97 v63.66,22.23 | 63.66,6.99 v64.61,6.99 | v37.94,10.16 v40.16,10.16 | v25.56,10.16 16.67,10.16 1.11,25.72 1.11,29.53 1.11,39.37 1.11,54.61 1.11,78.11 1.11,82.55 1.11,87.31 1.11,112.71 M5.1 8.41,120.02 8.41,121.92 15.4,128.91 33.18,128.91 v35.09,130.81 | 63.66,6.99 83.34,6.99 85.89,4.45 92.87,4.45 96.05,7.62 101.12,7.62 118.91,25.4 118.91,30.8 118.91,46.99 118.91,62.23 118.91,73.03 118.91,77.47 118.91,81.92
  Bottom 0.254: M2.1 6.97,86.85 v6.51,87.31 | v3.02,33.34 5.18,33.34 M3.1 | M1.1 112.95,75.01 112.87,74.93 v112.87,73.03 | M4.1 104.3,33.56 104.3,34.29 102.71,34.29 v101.76,33.34
  Bottom 0.813: R118.2 36.67,129.54 35.4,130.81 v35.09,130.81
  pour Top (no thermals): 40.16,6.35 44.61,6.35 46.83,8.57 45.56,9.84 40.8,9.84 40.8,8.89 40.16,8.26
+5V-A  (via drill 0.3)
  Top 0.254: C127.1 v86.52,13.65 87.16,14.29 87.16,16.51 87.53,16.89 IC37.24
  Bottom 0.254: v86.52,13.65 C127.1
+5V-LOW
  Top 0.254: 50.33,8.57 R164.2 | C117.1 50.33,6.99 | C117.1 50.33,6.35 50.33,6.99 | 50.33,6.99 50.33,8.57 | 50.33,8.57 50.33,8.89 | R160.1 58.9,5.4 58.58,5.71 | R160.1 59.53,5.71 | IC33.4 61.75,6.99 61.75,5.4 59.22,5.4 R160.1 | IC34.4 48.28,7.12 49.05,6.35 C117.1
  Top 0.813: 50.33,8.89 54.14,8.89 57.31,5.71 58.58,5.71
  pour Top (no thermals): 50.96,5.08 50.96,7.62 51.28,7.94 51.28,9.53 50.01,9.53 50.01,8.26 49.37,7.62 48.42,7.62 48.42,5.08
+5V-SHUNT  (via drill 0.3)
  Top 0.254: IC33.1 | IC33.1 63.66,9.53 | v64.93,20.32 64.93,12.7 R163.2 IC33.1
  Bottom 0.254: v64.93,20.32 R190.1
B0  (via drill 0.3)
  Top 0.254: IC29.100 66.5,83.81 66.52,83.82 66.52,91.12 65.88,91.76 64.93,91.76 58.26,85.09 v53.82,85.09 | v45.88,46.35 45.88,46.15 SW1.3 | SW1.4 43.34,51.75 v45.88,51.75
  Bottom 0.254: v53.82,85.09 53.5,85.09 51.59,83.19 51.59,78.42 45.88,72.71 v45.88,51.75 v45.88,46.35
B1  (via drill 0.3)
  Top 0.254: IC29.7 67.5,97.51 63.98,93.98 v58.58,93.98 | SW2.4 43.02,67.94 v45.24,67.94 | SW2.3 44.72,59.16 v45.24,59.69
  Bottom 0.254: v58.58,93.98 56.04,93.98 50.96,88.9 50.96,78.74 45.24,73.03 v45.24,67.94 v45.24,59.69
BD-CS
  Top 0.254: IC29.63 56.87,89.09 57.31,89.53 57.31,98.11 50.96,104.46 50.33,104.46 50.01,104.78 50.01,106.68 47.15,106.68 47.15,117.16 49.05,119.06 51.59,121.6 54.14,124.14 BD.2
BD-IRQ
  Top 0.152: IC29.55 51.09,93.03 44.29,93.03 43.98,92.71
  Top 0.254: 43.98,92.71 43.66,92.71 43.02,92.08 42.39,92.08 40.8,93.66 40.8,95.89 43.34,98.42 43.34,119.38 41.44,121.28 BD.7
BD-RST
  Top 0.254: IC29.37 50.78,102.09 46.52,106.36 46.52,117.47 48.74,119.7 51.28,122.24 51.59,122.56 BD.3
BUZZ  (via drill 0.3)
  Top 0.152: v42.7,95.89 43.98,95.89 45.88,97.79 49.69,97.79 49.99,98.09 IC29.45
  Top 0.254: v33.18,118.75 33.18,122.56 28.73,127 v23.02,127
  Bottom 0.254: v33.18,118.75 33.18,100.01 35.4,97.79 40.16,97.79 v42.7,95.89 | v23.02,127 22.07,127 R122.1
C1-A  (via drill 0.3)
  Top 0.254: C124.1 v86.52,11.75 86.52,12.06 89.44,14.98 IC37.25
  Bottom 0.254: v86.52,11.75 C124.1
C2-A  (via drill 0.3)
  Top 0.254: C125.1 v86.52,9.84 89.69,13.02 89.69,14.29 90.23,14.83 IC37.26
  Bottom 0.254: v86.52,9.84 C125.1
C3-A  (via drill 0.3)
  Top 0.254: C129.1 v86.52,7.94 90.33,11.75 90.33,13.97 91.03,14.68 IC37.27
  Bottom 0.254: v86.52,7.94 C129.1
C4-A  (via drill 0.3)
  Top 0.254: C130.1 v86.52,6.03 90.97,10.48 90.97,13.65 91.83,14.52 IC37.28
  Bottom 0.254: v86.52,6.03 C130.1
CELL1
  Bottom 0.406: BAT2#.1 R174.2
CELL1-ADC
  Bottom 0.254: R194.1 R176.2 R174.1
CELL2
  Bottom 0.406: BAT2+.P$1 R171.2
  pour Bottom (no thermals): 64.3,2.54 64.93,3.17 74.45,3.17 75.09,2.54 75.09,1.27 74.45,0.64 64.93,0.64 64.3,1.27
  pour Top (no thermals): 64.3,2.54 64.93,3.17 74.45,3.17 75.09,2.54 75.09,1.27 74.45,0.64 64.93,0.64 64.3,1.27
CELL2-ADC
  Bottom 0.254: R193.1 73.82,11.11 73.82,10.48 73.82,9.53 R177.2 R171.1
CELL3
  Bottom 0.406: BAT1#.1 63.98,4.13 69.69,4.13 70.01,4.45 R170.2
CELL3-ADC
  Bottom 0.254: R182.1 R178.2 R170.1
CELL4-ADC
  Bottom 0.254: R180.1 66.2,10.48 68.11,7.93 R179.2 R169.1
DECT-CTSO  (via drill 0.3)
  Top 0.152: IC29.117 75.39,88.59 75.41,88.58 75.41,87.63 75.72,87.31 77,87.31 80.17,84.14 v80.17,81.92
  Top 0.254: IC26.29 73.82,36.2 74.45,36.83 74.45,37.78 73.82,38.42 v73.82,39.37
  Bottom 0.254: v80.17,81.92 80.17,70.8 78.9,69.53 78.9,57.78 73.82,52.7 v73.82,39.37
DECT-DCDO  (via drill 0.3)
  Top 0.254: IC29.80 56.5,80.79 55.09,79.38 v55.09,77.47 | v74.45,38.73 75.09,38.1 IC26.31
  Bottom 0.254: v55.09,77.47 69.38,63.18 69.38,41.27 68.11,40.01 68.11,38.73 v74.45,38.73
DECT-DSRO  (via drill 0.3)
  Top 0.254: IC29.78 55.5,81.06 53.82,79.38 v53.82,77.47 | v73.82,28.57 IC26.30
  Bottom 0.254: v53.82,77.47 53.82,76.83 68.11,62.55 68.11,41.27 66.83,40.01 66.83,29.21 68.11,27.94 73.19,27.94 v73.82,28.57
DECT-DTRI  (via drill 0.3)
  Top 0.254: IC29.79 56,80.93 54.45,79.38 v54.45,78.11 | v70.01,28.57 IC26.24
  Bottom 0.254: v54.45,78.11 54.45,77.15 68.74,62.87 68.74,41.27 67.47,40.01 67.47,31.11 v70.01,28.57
DECT-RSTBI  (via drill 0.3)
  Top 0.254: IC29.123 70.8,91.59 70.33,91.12 70.33,84.45 71.28,83.5 71.28,81.6 72.55,80.33 v72.55,77.15 | IC26.21 v68.74,39.37
  Bottom 0.254: v72.55,77.15 72.55,74.93 71.28,73.66 71.28,41.91 v68.74,39.37
DECT-RTSI  (via drill 0.3)
  Top 0.152: IC29.118 75.53,89.09 75.72,88.9 75.72,87.95 76.04,87.63 77.31,87.63 80.81,84.14 v80.81,82.55
  Top 0.254: IC26.23 70.01,41.27 v74.45,41.27
  Bottom 0.254: v80.81,82.55 80.81,70.17 79.53,68.9 79.53,57.47 74.45,52.39 v74.45,41.27
DECT-RXDO  (via drill 0.3)
  Top 0.254: IC26.25 71.28,36.2 70.64,36.83 v70.64,40.01 | IC29.122 71.25,91.09 70.96,90.81 70.96,84.45 71.92,83.5 71.92,81.6 73.5,80.01 v73.5,77.15
  Bottom 0.254: v73.5,77.15 73.5,74.61 71.92,73.03 71.92,41.27 v70.64,40.01
DECT-TXDI  (via drill 0.3)
  Top 0.152: IC29.119 75.67,89.59 76.04,89.22 76.04,88.27 76.36,87.95 77.63,87.95 81.44,84.14 v81.44,83.19
  Top 0.254: v71.28,28.57 IC26.26 | v80.17,60.33 77,60.33 64.93,48.26 64.93,38.73 66.2,37.47 v68.11,37.47
  Bottom 0.254: v81.44,83.19 81.44,69.53 80.17,68.26 v80.17,60.33 | v68.11,37.47 68.11,31.75 v71.28,28.57
EN  (via drill 0.3)
  Top 0.254: C118.1 | C118.1 v54.45,10.79 | C118.1 R164.1 50.33,10.48 50.01,10.48 48.78,9.26 IC34.5 | v61.12,41.27 61.12,42.38 Q37.C
  Bottom 0.254: v54.45,10.79 58.26,6.99 60.17,6.99 61.12,7.94 v61.12,41.27
EN5V  (via drill 0.3)
  Top 0.254: IC29.77 55,81.2 v53.18,79.38 | R166.1 51.91,42.55 v46.52,42.55
  Bottom 0.254: v53.18,79.38 53.18,79.06 46.52,72.39 v46.52,42.55
ENC1-A  (via drill 0.3)
  Top 0.254: ENC1.2 118.59,61.59 118.59,87 116.68,88.9 84.61,88.9 82.71,87 82.71,82.87 79.53,79.69 v75.41,79.69 | IC29.96 64.5,86.15 v63.66,87
  Bottom 0.254: v63.66,87 70.96,79.69 v75.41,79.69
ENC1-B  (via drill 0.3)
  Top 0.254: ENC1.4 119.22,57.15 119.22,87.31 117,89.53 84.3,89.53 82.08,87.31 82.08,82.87 79.53,80.33 v74.77,80.33 | IC29.97 65,86.6 v64.61,87
  Bottom 0.254: v64.61,87 71.28,80.33 v74.77,80.33
ENC2-A  (via drill 0.3)
  Top 0.152: IC29.34 54,104.91 53.5,105.41 53.18,105.41 v52.55,106.05
  Top 0.254: v3.02,92.08 31.27,92.08 39.53,100.33 39.53,103.82 v41.75,106.05 | IC3.4 6.16,66.99 v5.24,66.99
  Bottom 0.254: v3.02,92.08 2.06,92.08 0.79,90.81 0.79,67.94 5.24,67.94 v5.24,66.99 | v41.75,106.05 v52.55,106.05
ENC2-B  (via drill 0.3)
  Top 0.152: IC29.35 53.51,104.77 53.18,105.09 v52.55,105.09
  Top 0.254: v2.38,91.44 31.27,91.44 40.16,100.33 40.16,103.5 v41.75,105.09 | v7.14,69.22 7.14,70.51 IC4.4
  Bottom 0.254: v2.38,91.44 1.43,90.49 1.43,69.53 6.83,69.53 v7.14,69.22 | v41.75,105.09 v52.55,105.09
ENC3-A  (via drill 0.3)
  Top 0.152: IC29.60 49.58,90.59 48.1,92.08 45.88,92.08 43.98,90.17 v36.35,90.17
  Top 0.254: ENC3.2 0.79,41.91 0.79,88.27 3.34,90.81 v21.75,90.81
  Bottom 0.254: v21.75,90.81 35.72,90.81 v36.35,90.17
ENC3-B  (via drill 0.3)
  Top 0.254: ENC3.4 1.43,46.99 1.43,87.95 3.65,90.17 v22.38,90.17 | IC29.64 49.07,88.59 48.42,87.95 45.24,87.95 44.29,88.9 38.58,88.9 37.94,89.53 v35.72,89.53
  Bottom 0.254: v35.72,89.53 35.09,90.17 v22.38,90.17
ENC4-A  (via drill 0.3)
  Top 0.152: IC29.136 73.81,98.09 74.77,99.06 v83.98,99.06
  Bottom 0.254: ENC4.2 118.59,46.35 118.59,89.53 115.41,92.71 87.47,92.71 83.98,96.2 v83.98,99.06
ENC4-B  (via drill 0.3)
  Top 0.152: IC29.137 73.67,98.59 74.45,99.38 77.95,99.38 78.27,99.69 v84.61,99.69
  Bottom 0.254: ENC4.4 119.22,41.91 119.22,89.85 115.73,93.34 87.79,93.34 84.61,96.52 v84.61,99.69
FLT1
  Top 0.254: R1.2 86.83,76.52 85.89,75.56 83.34,75.56 82.39,76.52 R4.1
  Top 0.61: R1.2 IC1.8
FLT2  (via drill 0.3)
  Top 0.406: IC2.8 v32.23,78.11 | v32.23,86.36 R19.2
  Bottom 0.254: v32.23,78.11 R22.1
  Bottom 0.406: v32.23,78.11 v32.23,86.36
FLT3  (via drill 0.3)
  Top 0.406: IC5.8 31.27,46.99 32.55,45.72 35.09,45.72 36.04,44.77 | R37.2 35.72,33.66 36.99,34.92 36.99,43.81 36.04,44.77 | v36.99,48.26 36.99,45.72 36.04,44.77
  Bottom 0.406: R40.1 36.99,49.85 v36.99,48.26
FLT4  (via drill 0.3)
  Top 0.406: v87.79,46.99 IC6.8 | R55.2 93.19,32.39 v90.97,34.61
  Bottom 0.254: v87.79,46.99 R58.1
  Bottom 0.406: v87.79,46.99 89.06,46.99 89.06,36.51 v90.97,34.61
FLT5  (via drill 0.3)
  Top 0.305: 29.37,107.31 28.73,106.68 28.73,96.84 30.32,96.84 v30.96,96.84 R73.2
  Top 0.406: 29.37,107.31 IC7.8
  Bottom 0.254: R76.1 31.27,96.52 v30.96,96.84
GND  (via drill 0.3)
  Top 0.152: IC29.138 71,99.09 v70.96,99.06 | 52.79,96.59 52.87,96.52
  Top 0.254: SDCARD.6 79.22,125.73 79.22,126.36 82.39,126.36 82.39,125.09 | 82.39,125.09 SDCARD.COM | 82.39,125.09 v83.66,125.09 | IC24.16 IC24.17 64.92,69.2 v64.93,69.22 | 63.66,124.78 63.03,124.78 | 63.03,124.78 62.71,124.78 | 63.03,124.78 62.07,125.73 C83.2 64.93,131.76 64.93,133.35 63.6,133.35 IC25.16 IC25.17 | v63.66,123.51 63.66,124.78 | 63.66,124.78 C84.- | Q32.E 53.18,39.69 v54.77,39.69 | v86.52,27.94 IC26.50 | v72.55,24.13 C81.2 | C82.2 v72.55,40.64 | C114.2 41.75,28.57 41.44,28.89 40.8,28.57 41.12,29.21 | C113.2 52.87,28.57 52.55,28.89 v51.91,28.89 | C112.2 52.87,21.91 53.82,20.95 v54.45,20.64 54.45,19.05 D23.A | v51.91,13.02 52.87,13.02 C118.2 | C117.2 52.87,6.03 53.82,5.08 v54.45,5.08 54.45,3.17 D25.A | C119.2 42.07,12.7 41.12,12.7 | R168.1 | 62.71,24.77 IC30.2 | R154.1 64.3,24.77 62.71,24.77 | v62.71,22.23 62.71,24.77 | v62.71,15.24 IC32.2 62.71,18.73 62.08,19.36 61.76,19.36 R162.1 | v62.71,8.26 IC33.2 62.71,10.48 R163.1 | 72.87,9.84 C122.2 | v72.87,9.53 72.87,9.84 | 72.87,9.84 73.19,10.16 C134.2 | 72.87,21.27 C132.2 | C123.2 72.55,20.95 72.87,21.27 | 72.87,21.27 v72.87,21.59 | C121.2 66.2,10.16 v65.56,9.53 | v66.2,19.05 C131.2 | C133.2 v78.9,18.1 | IC35.11 69.06,16.51 75.09,16.51 | 75.09,16.51 75.72,16.51 | 76.36,16.51 C133.2 | C133.2 | 75.09,16.51 IC36.11 | 76.36,16.51 IC36.9 | 75.72,16.51 IC36.10 | 75.72,16.51 76.36,16.51 | IC9.2 23.02,66.04 v22.38,66.67 C57.2 | IC12.2 23.02,62.23 v22.38,62.87 C67.2 | IC10.2 23.02,58.42 v22.38,59.05 C63.2 | v31.59,63.18 R111.1 C62.2 | v31.91,66.99 R99.1 C59.2 | v27.15,60.33 27.46,60.33 R103.1 C60.2 | C66.2 99.22,63.82 C56.2 98.91,65.41 98.9,65.41 98.27,66.04 IC8.2 v96.05,66.04 | R92.1 C58.2 v90.97,63.82
  Top 0.254: R108.1 C61.2 90.64,58.74 89.69,59.05 v89.69,61.28 | 98.27,59.69 C64.2 | C128.2 C126.2 C127.2 v83.34,18.73 | C124.2 C125.2 C129.2 C130.2 v83.34,4.76 | C19.2 3.33,85.09 3.34,85.09 v3.34,86.36 | C20.2 3.33,80.64 3.34,80.64 v3.34,81.92 | C21.2 3.33,76.2 3.34,76.2 v3.34,77.47 | v7.46,88.9 C18.2 | C32.2 v8.41,27.62 | C33.2 v12.86,27.62 | C31.2 v3.97,27.62 1.75,29.84 C30.2 | C8.2 v117.32,73.66 117.32,71.44 C7.2 | v117.32,78.11 C9.2 | v117,82.55 117,83.82 C10.2 | C42.2 v103.03,29.53 100.81,29.53 C41.2 | C43.2 v107.47,29.53 | C44.2 v111.92,29.53 | C52.2 7.14,120.33 v6.19,119.38 | C98.2 C97.2 55.5,106.47 IC29.31 IC29.30 | C98.2 v55.72,109.85 v55.72,109.86 | IC29.16 63,107.61 C109.2 v63.34,109.22 | IC29.143 75.1,101.59 C99.2 v76.99,100.97 v77,100.97 | IC29.130 75.25,95.09 C100.2 v77.31,94.3 | IC29.120 76.12,90.09 C101.2 v78.58,88.9 | IC29.107 70,79.69 C102.2 v69.38,77.15 | IC29.94 63.5,79.22 C103.2 v63.34,77.79 | IC29.83 58,79.43 C104.2 v57.63,77.47 | IC29.61 47.86,90.09 C106.2 v45.88,90.8 v45.88,90.81 | IC29.71 48.09,85.09 C105.2 v46.52,84.77 | IC29.38 49.06,101.59 C108.2 v46.52,102.87 | v46.52,96.52 C107.2 47.86,96.59 IC29.48 52.79,96.59 | 52.87,96.52 52.87,95.25 52.71,95.09 IC29.51 | C78.2 54.12,69.2 IC24.5 53.5,69.2 53.5,69.22 48.1,69.22 47.47,68.58 47.47,68.12 C79.- 47.15,67.31 v48.42,67.31 | IC24.2 55.09,71.6 v55.09,71.75 | C92.2 68.11,109.54 v67.79,109.86 71.28,109.86 | 71.28,109.86 C110.- | C95.2 69.69,113.34 71.28,111.76 71.28,109.86 | C96.2 v60.8,109.86 | C94.2 49.37,117.47 v50.64,117.47 | C93.2 67.79,117.47 v69.38,117.47 | C91.2 57.63,108.58 C98.2 | RESET.1 80.81,111.81 v80.81,113.03 | SW2.2 38.26,68.53 38.26,67.94 v36.99,67.94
